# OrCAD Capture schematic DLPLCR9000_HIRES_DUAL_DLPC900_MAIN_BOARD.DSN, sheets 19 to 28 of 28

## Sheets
19 P01-Title
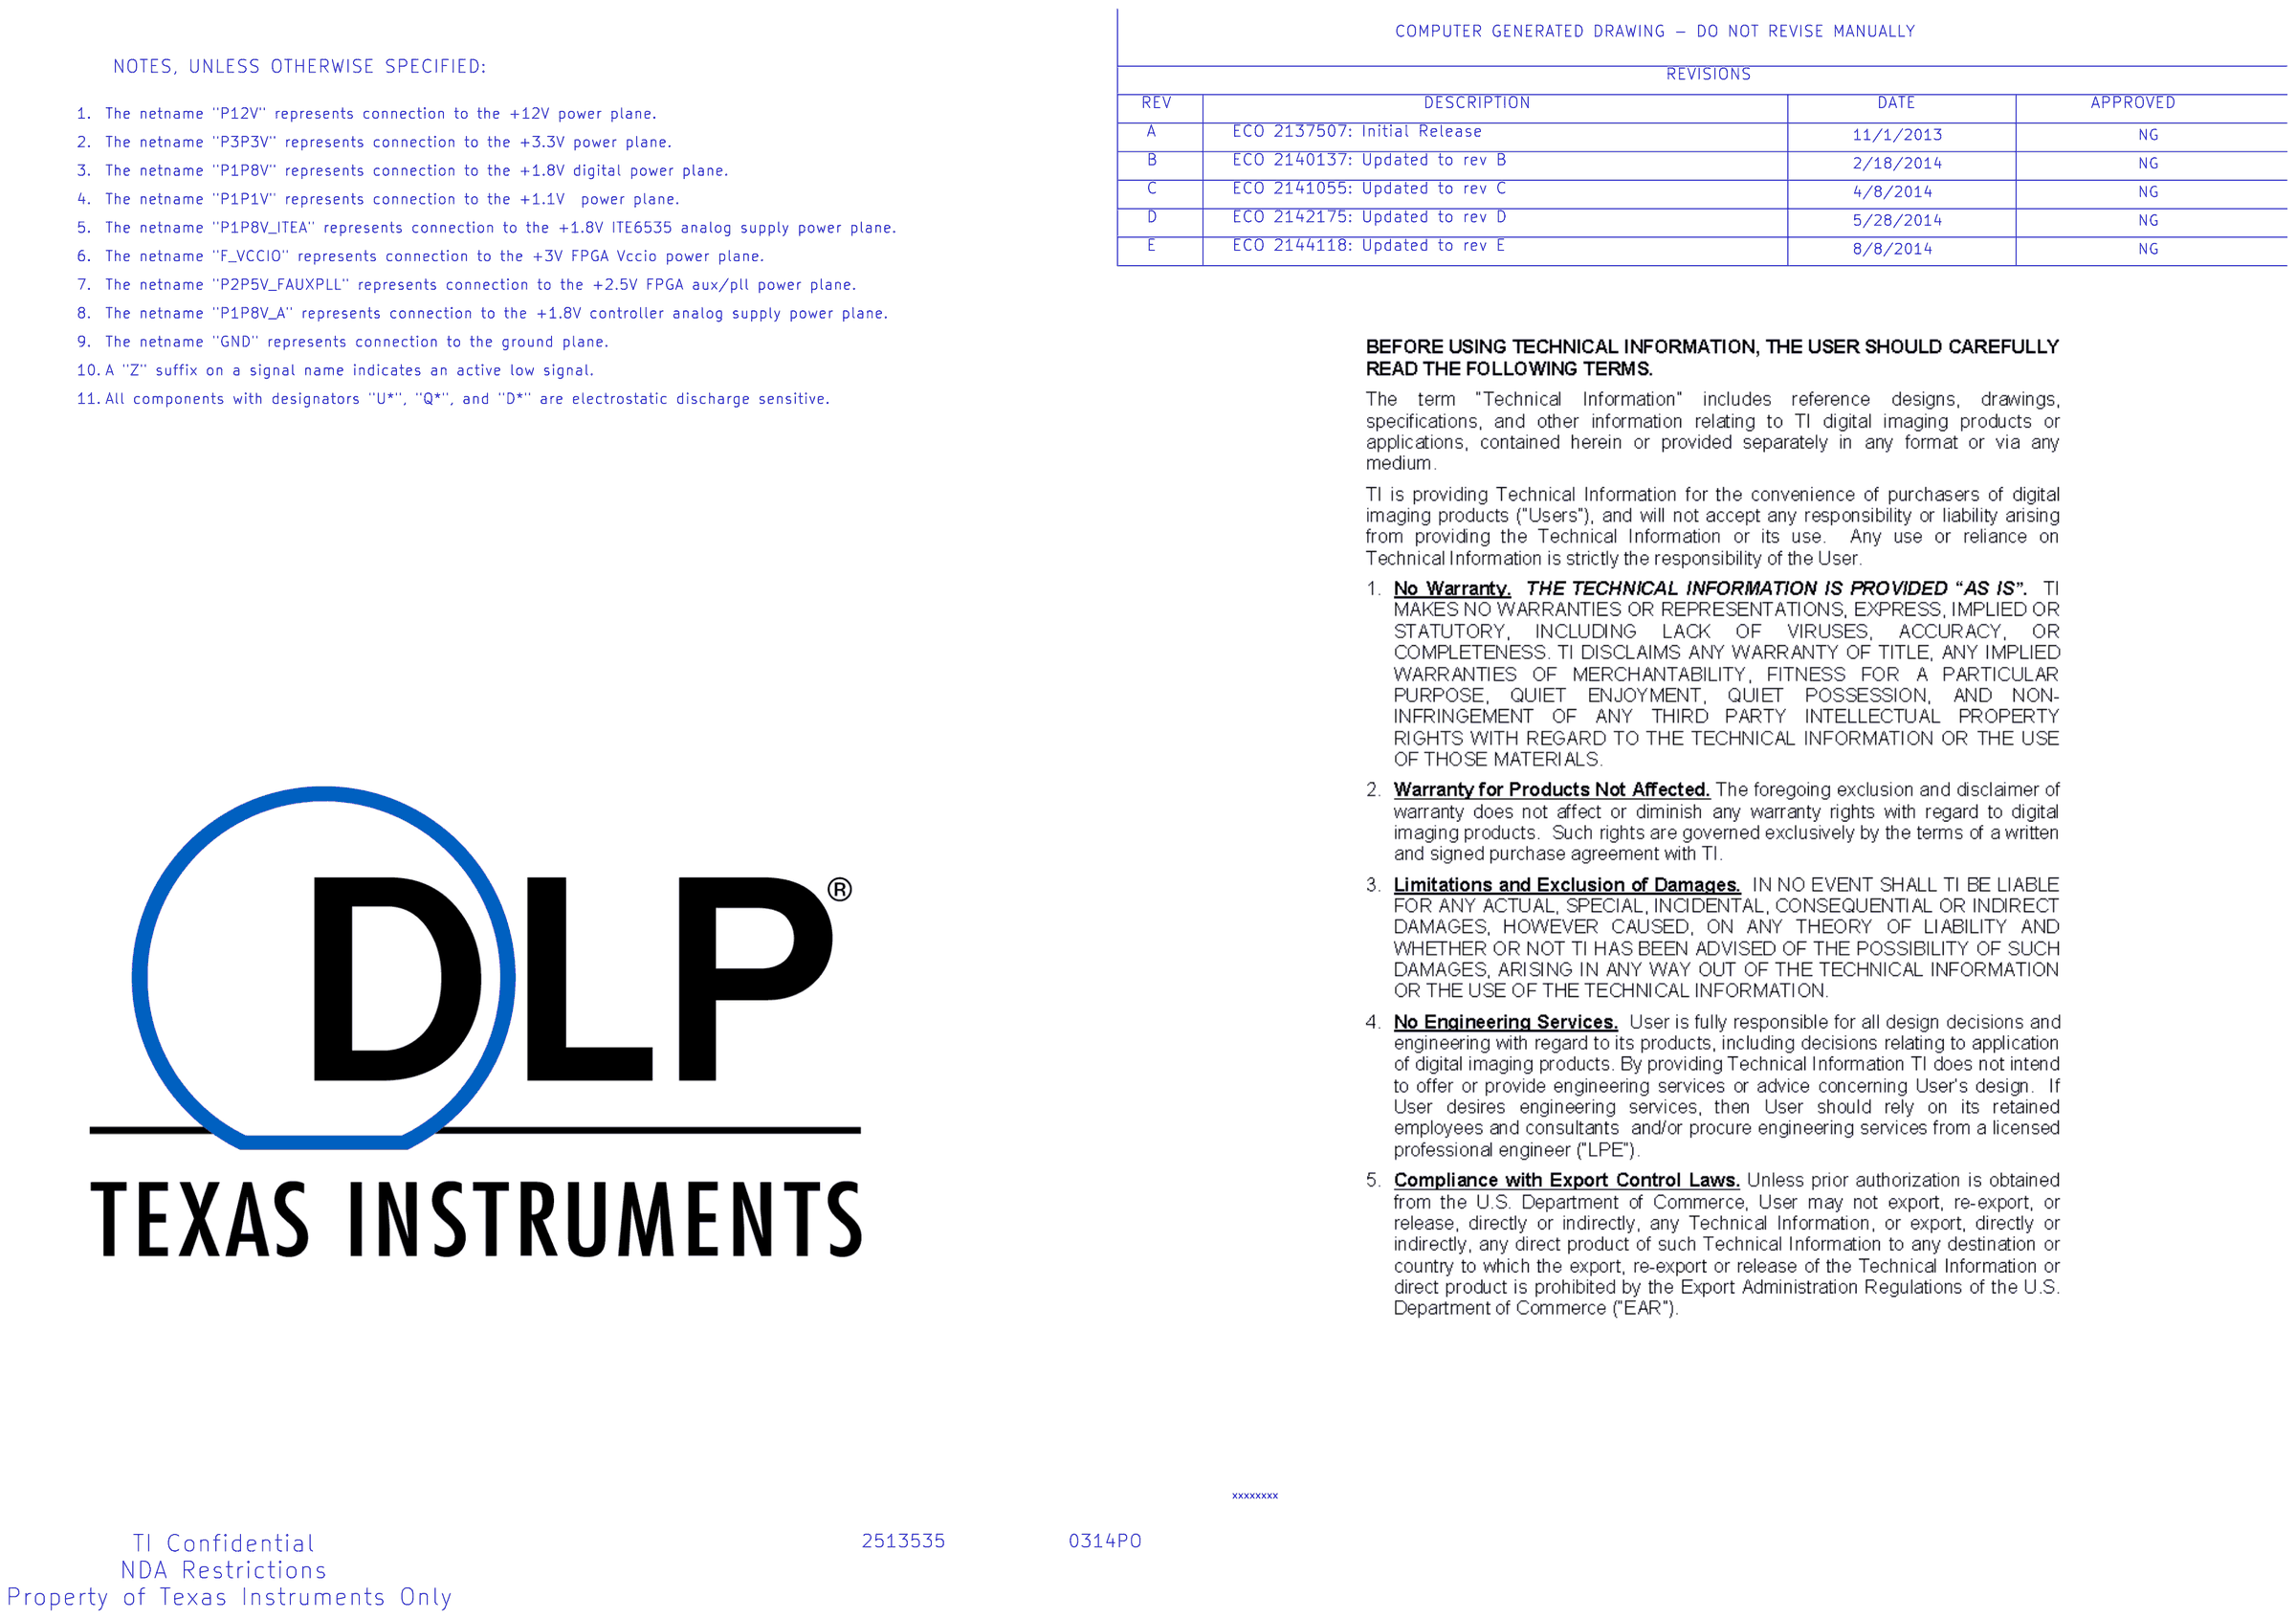
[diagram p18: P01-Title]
20 P03-Table Of Contents
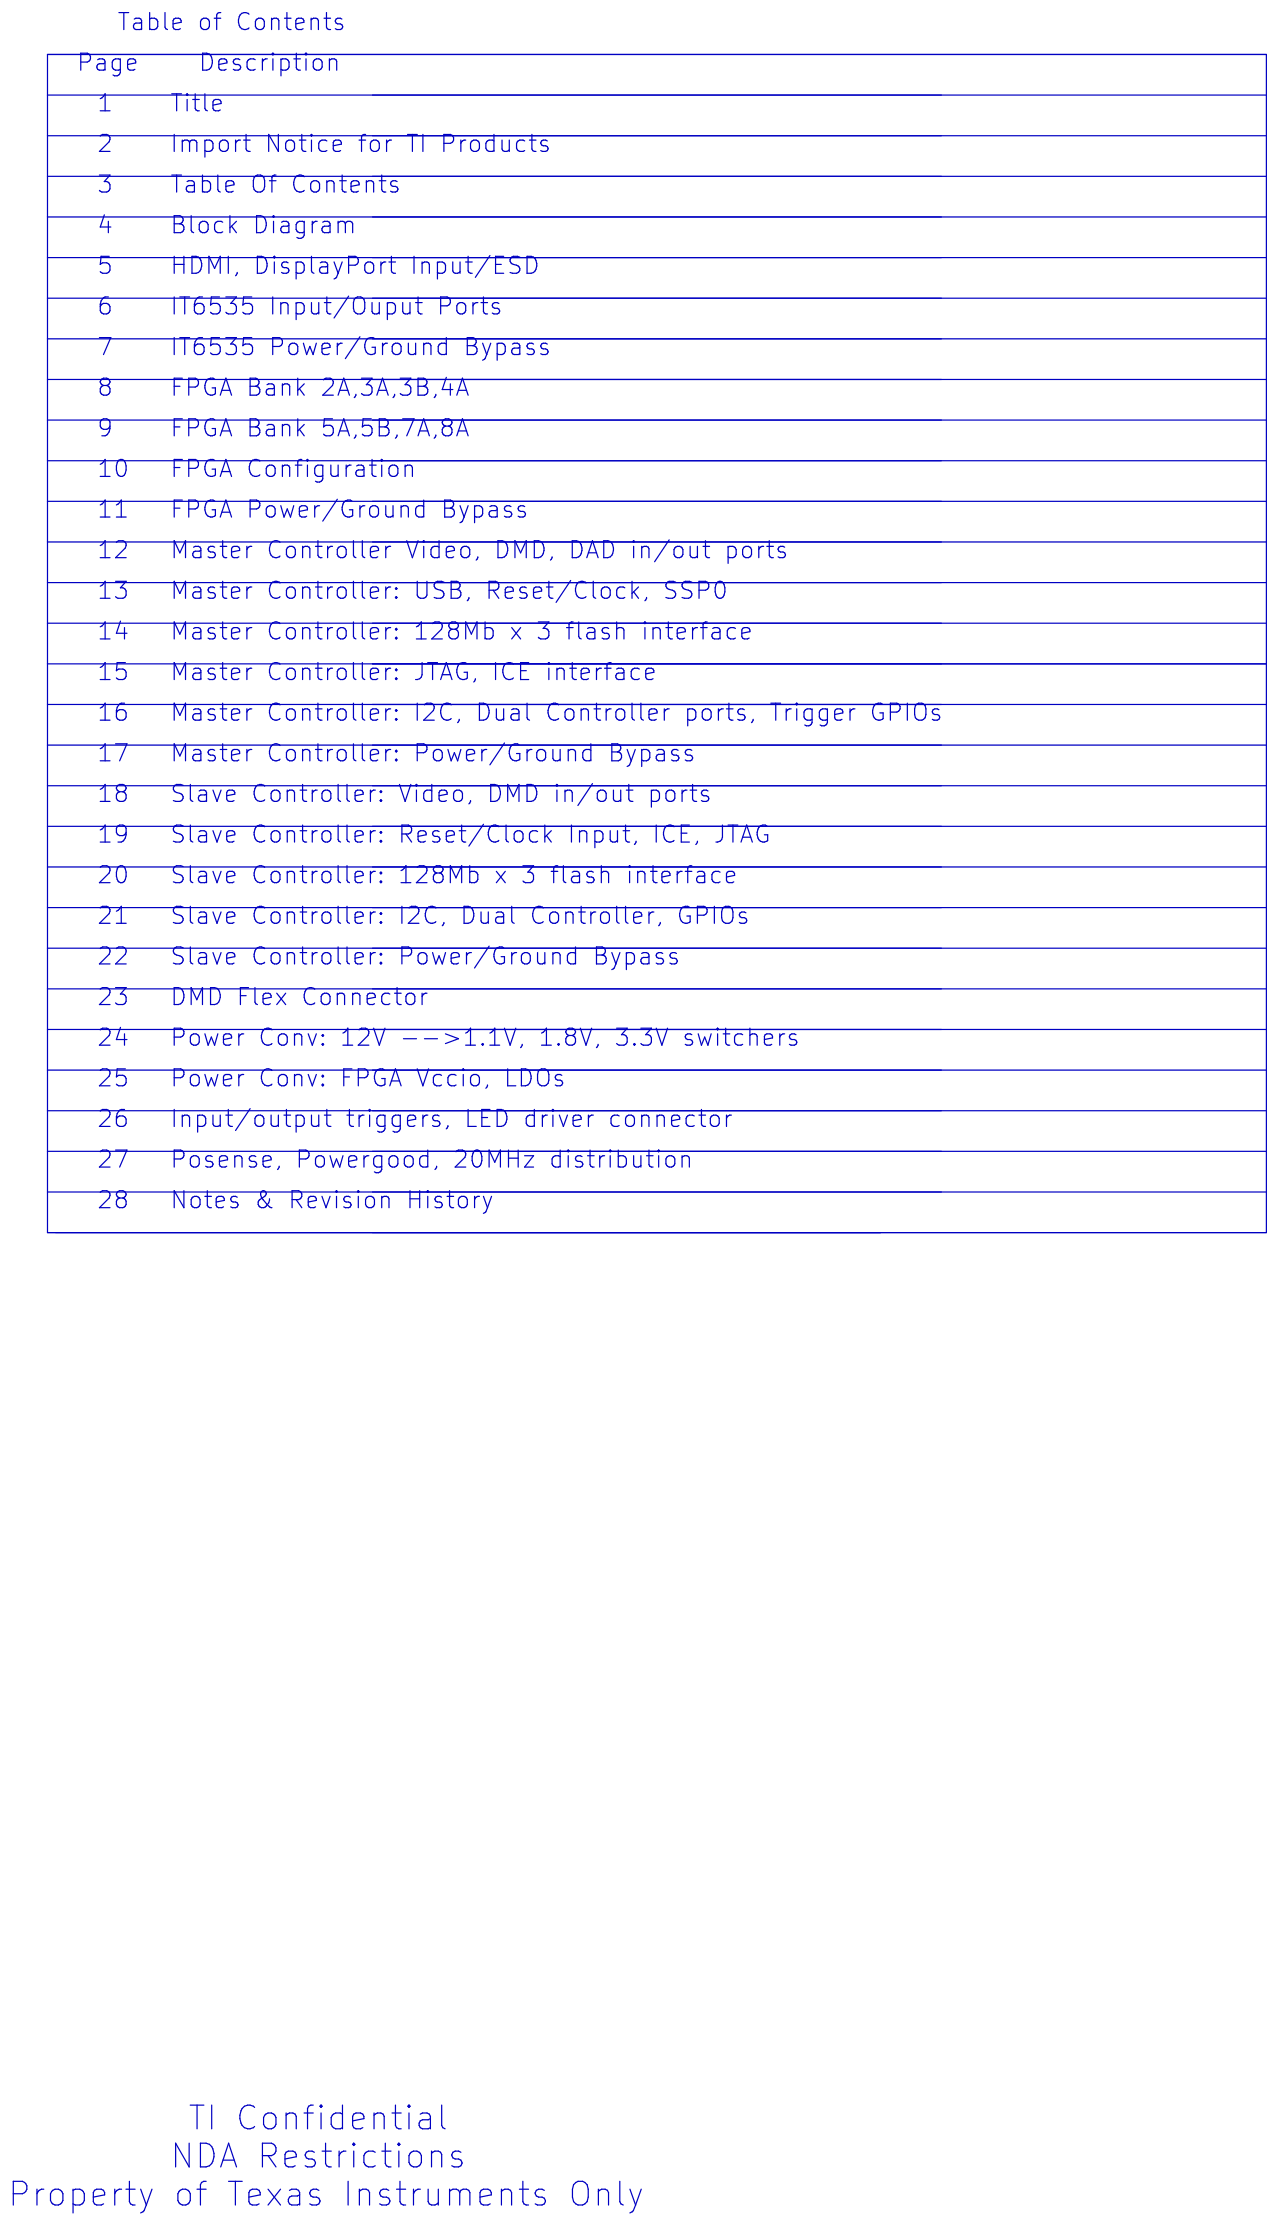
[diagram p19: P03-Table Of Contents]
21 P04-Block Diagram
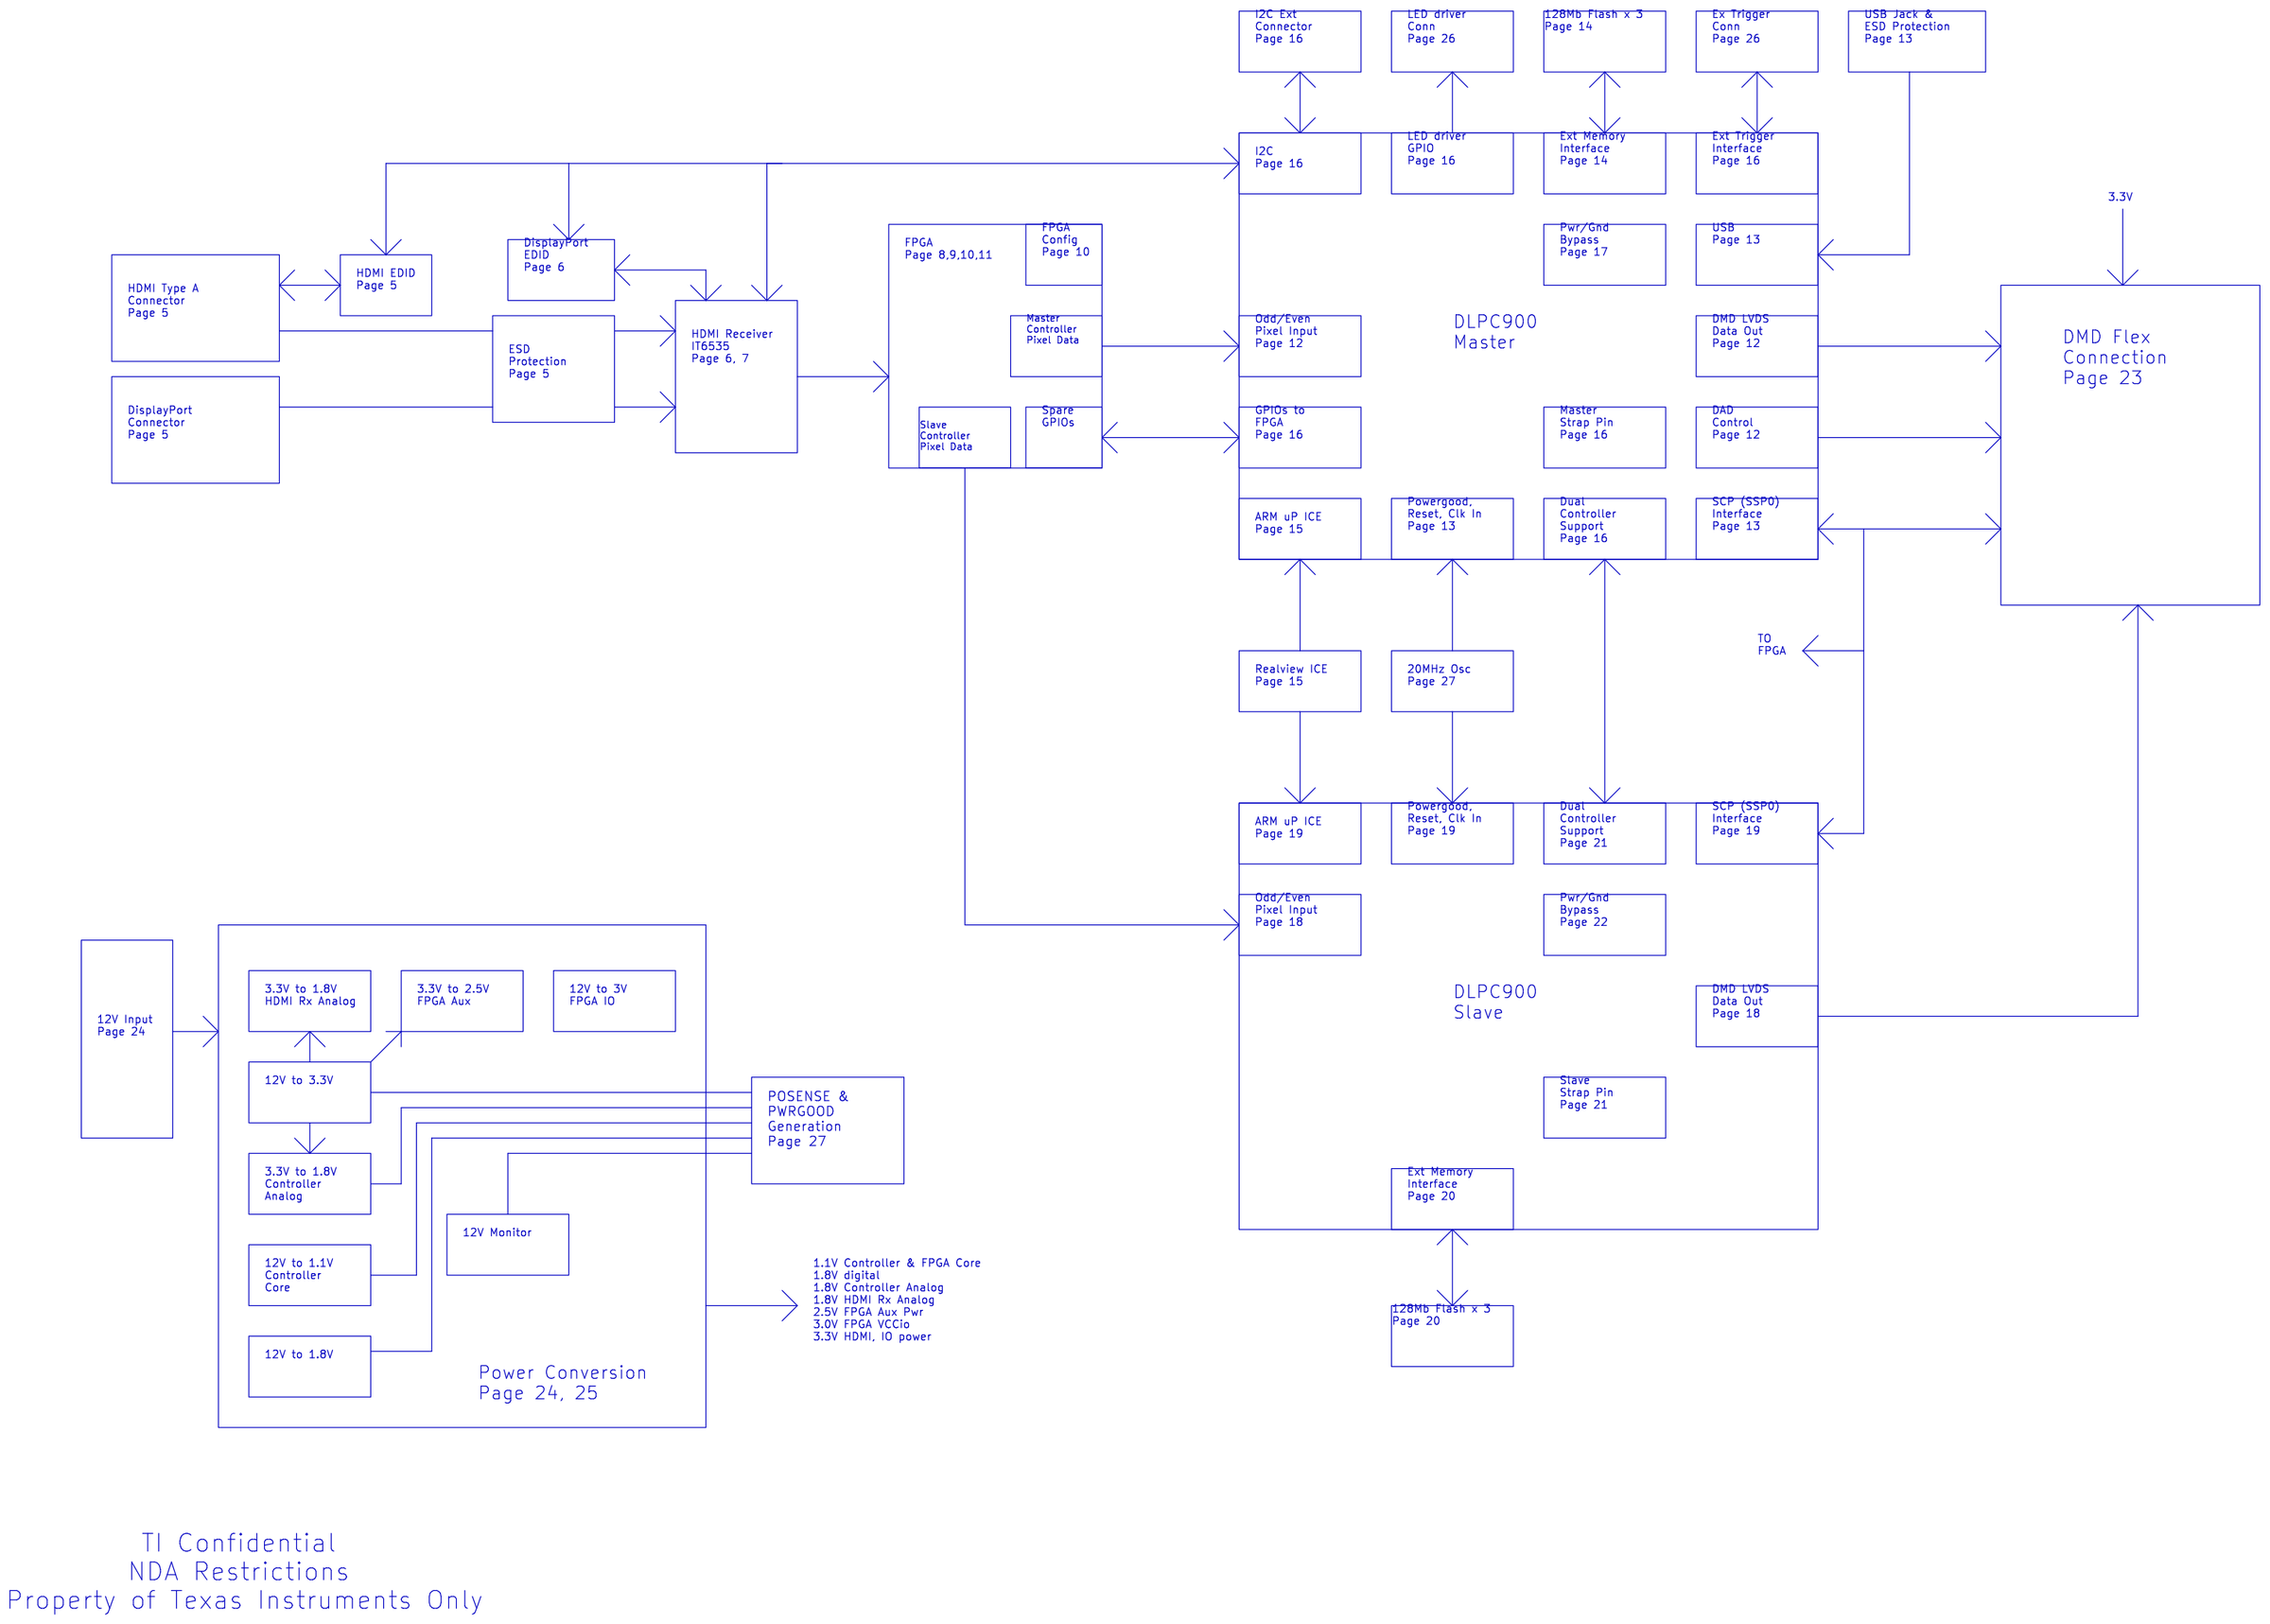
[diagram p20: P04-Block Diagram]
22 P06-IT6535 Input Output Ports: size A3
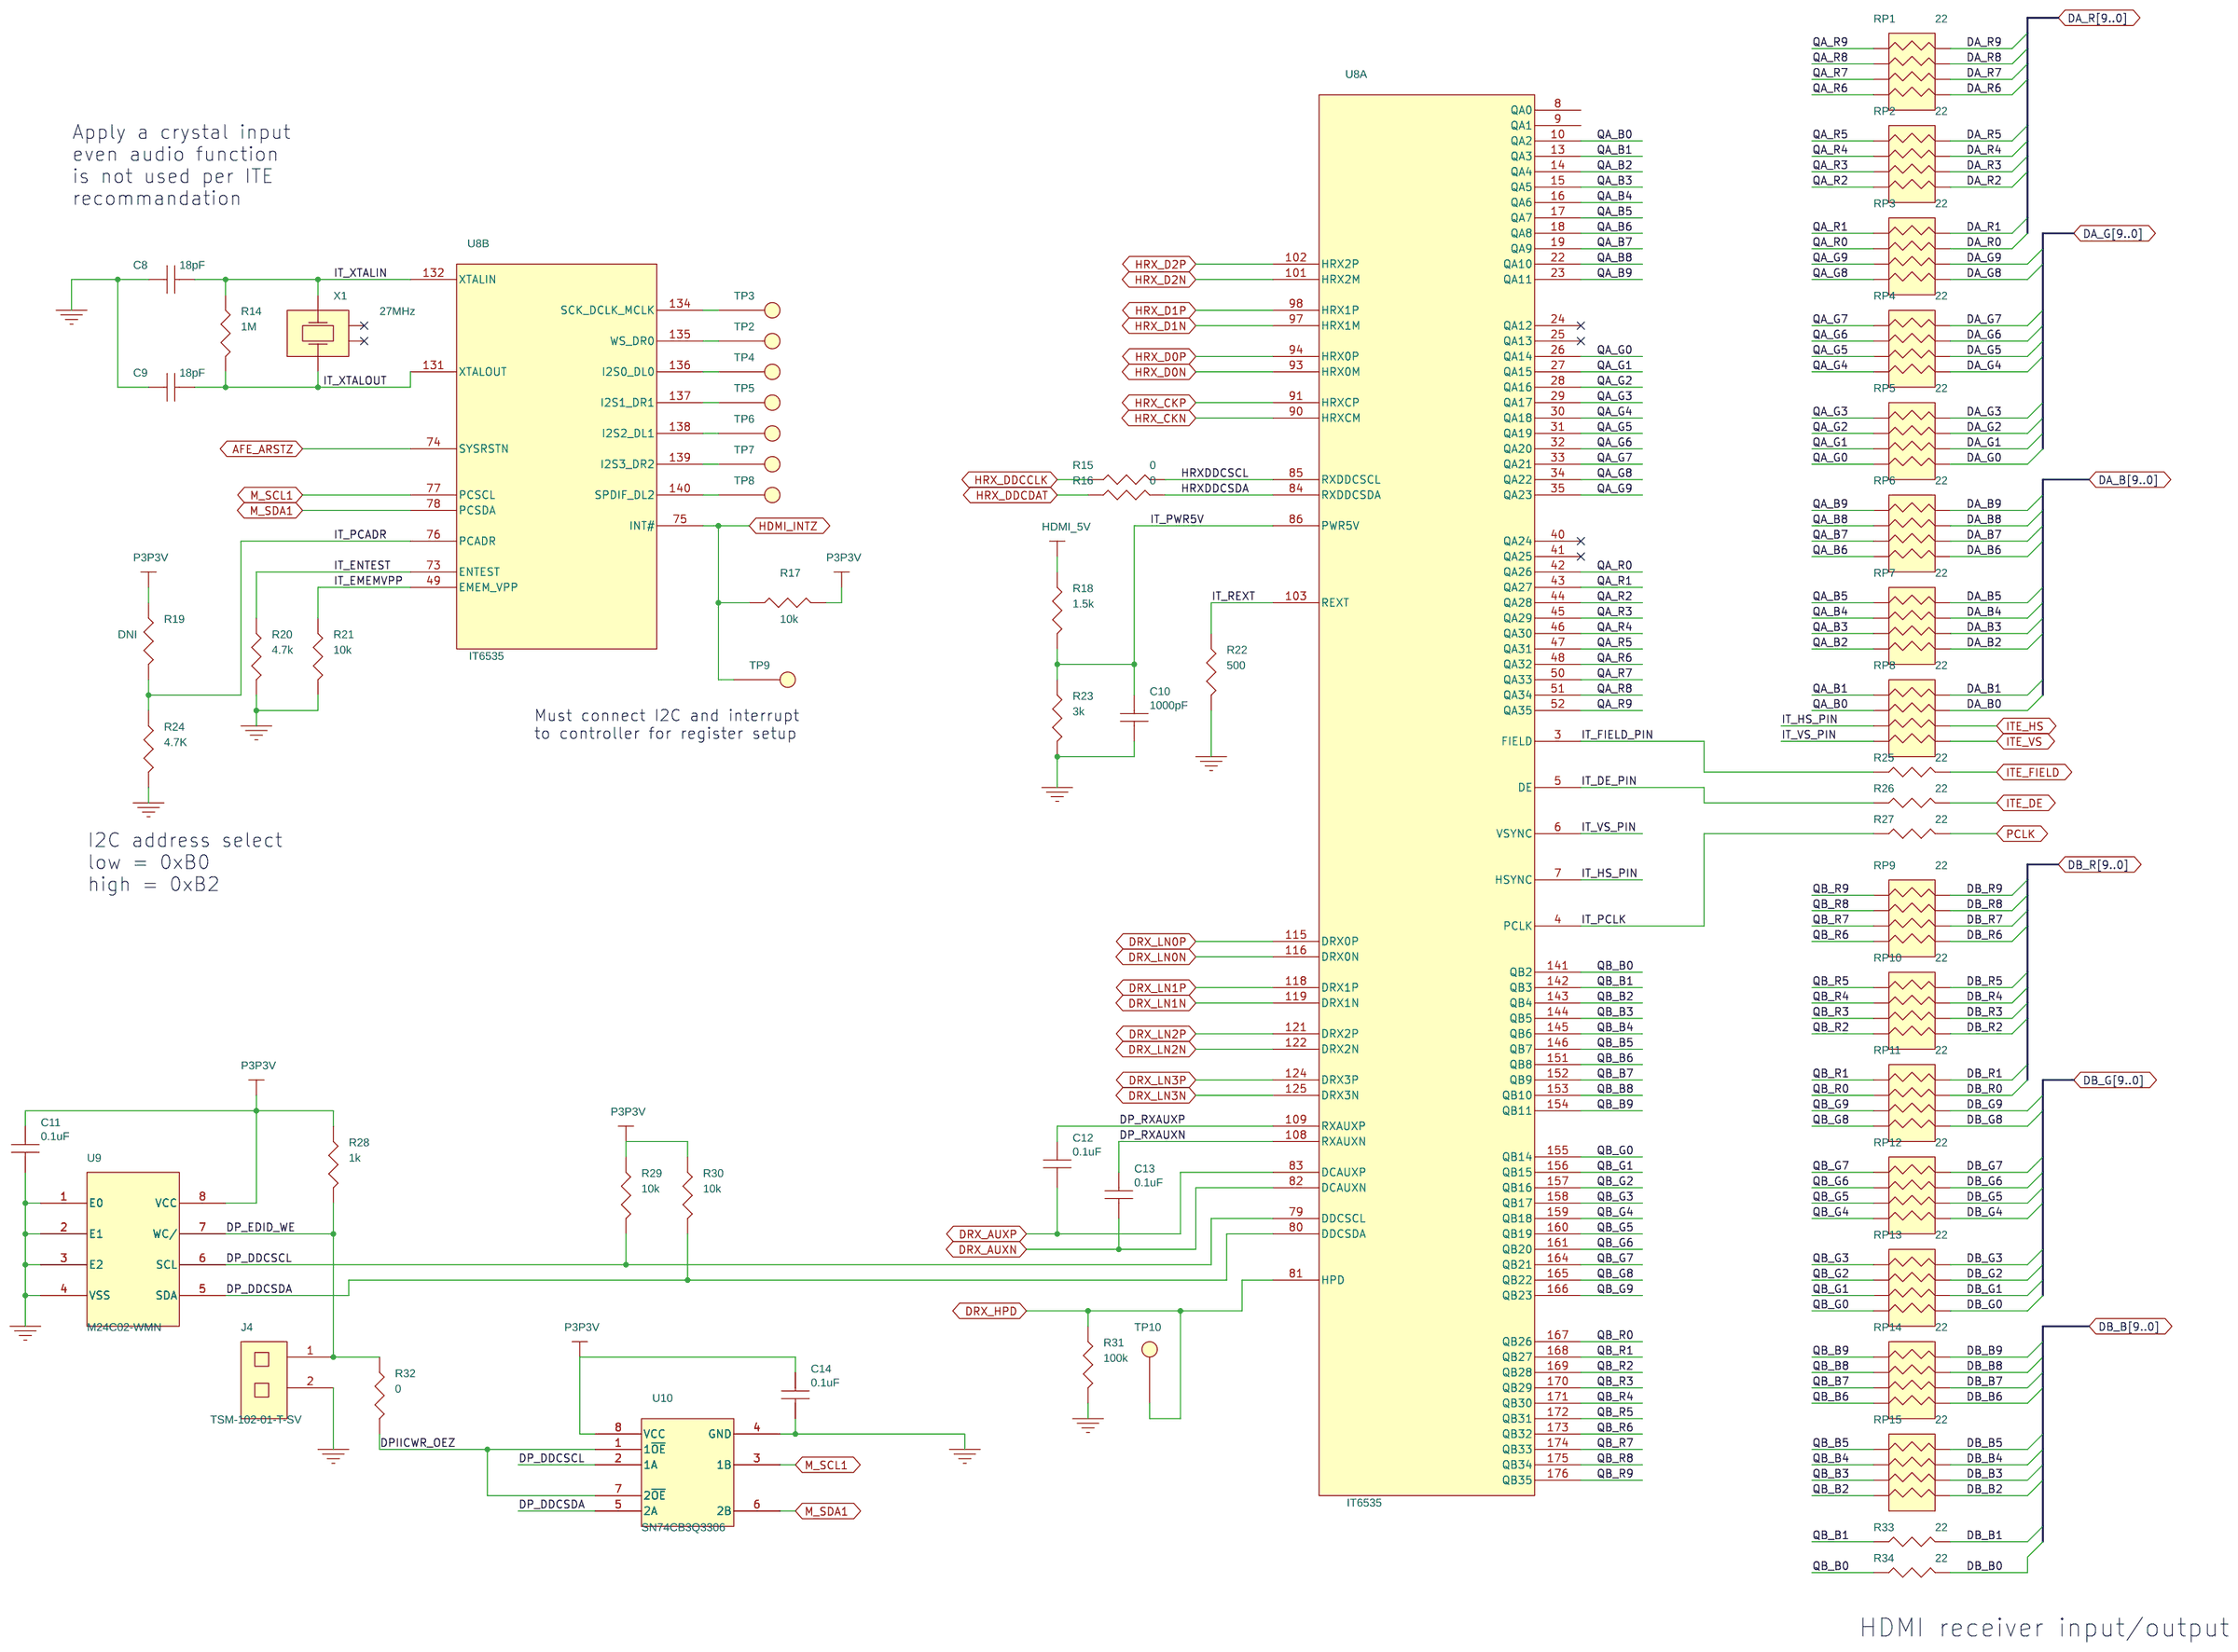
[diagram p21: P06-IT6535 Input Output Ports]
23 P28-Notes and Revision
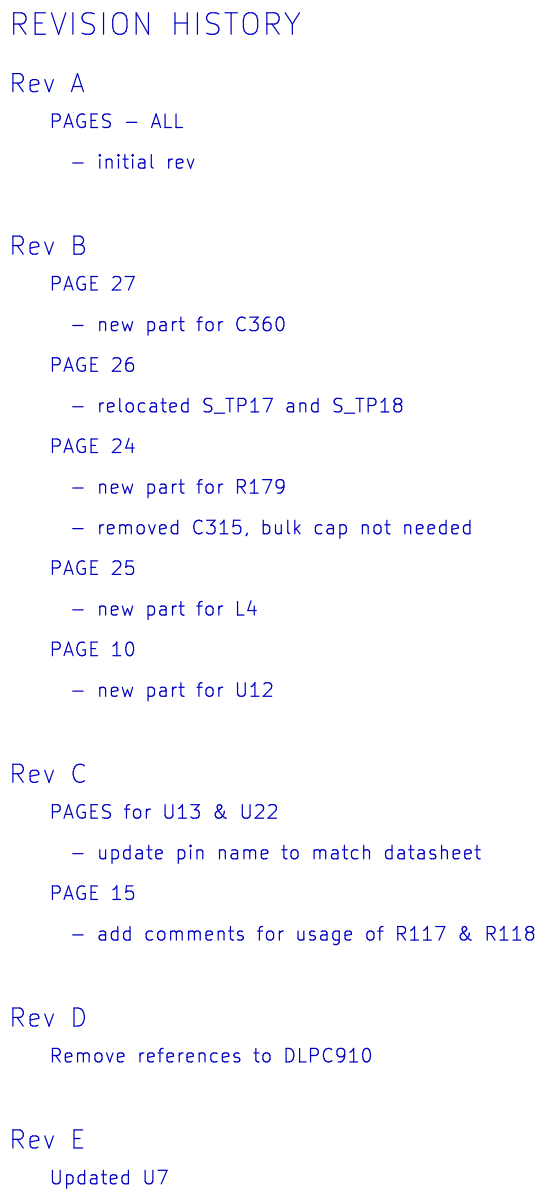
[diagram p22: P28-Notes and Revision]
24 P07-IT6535 Pwr/Gnd: size A3
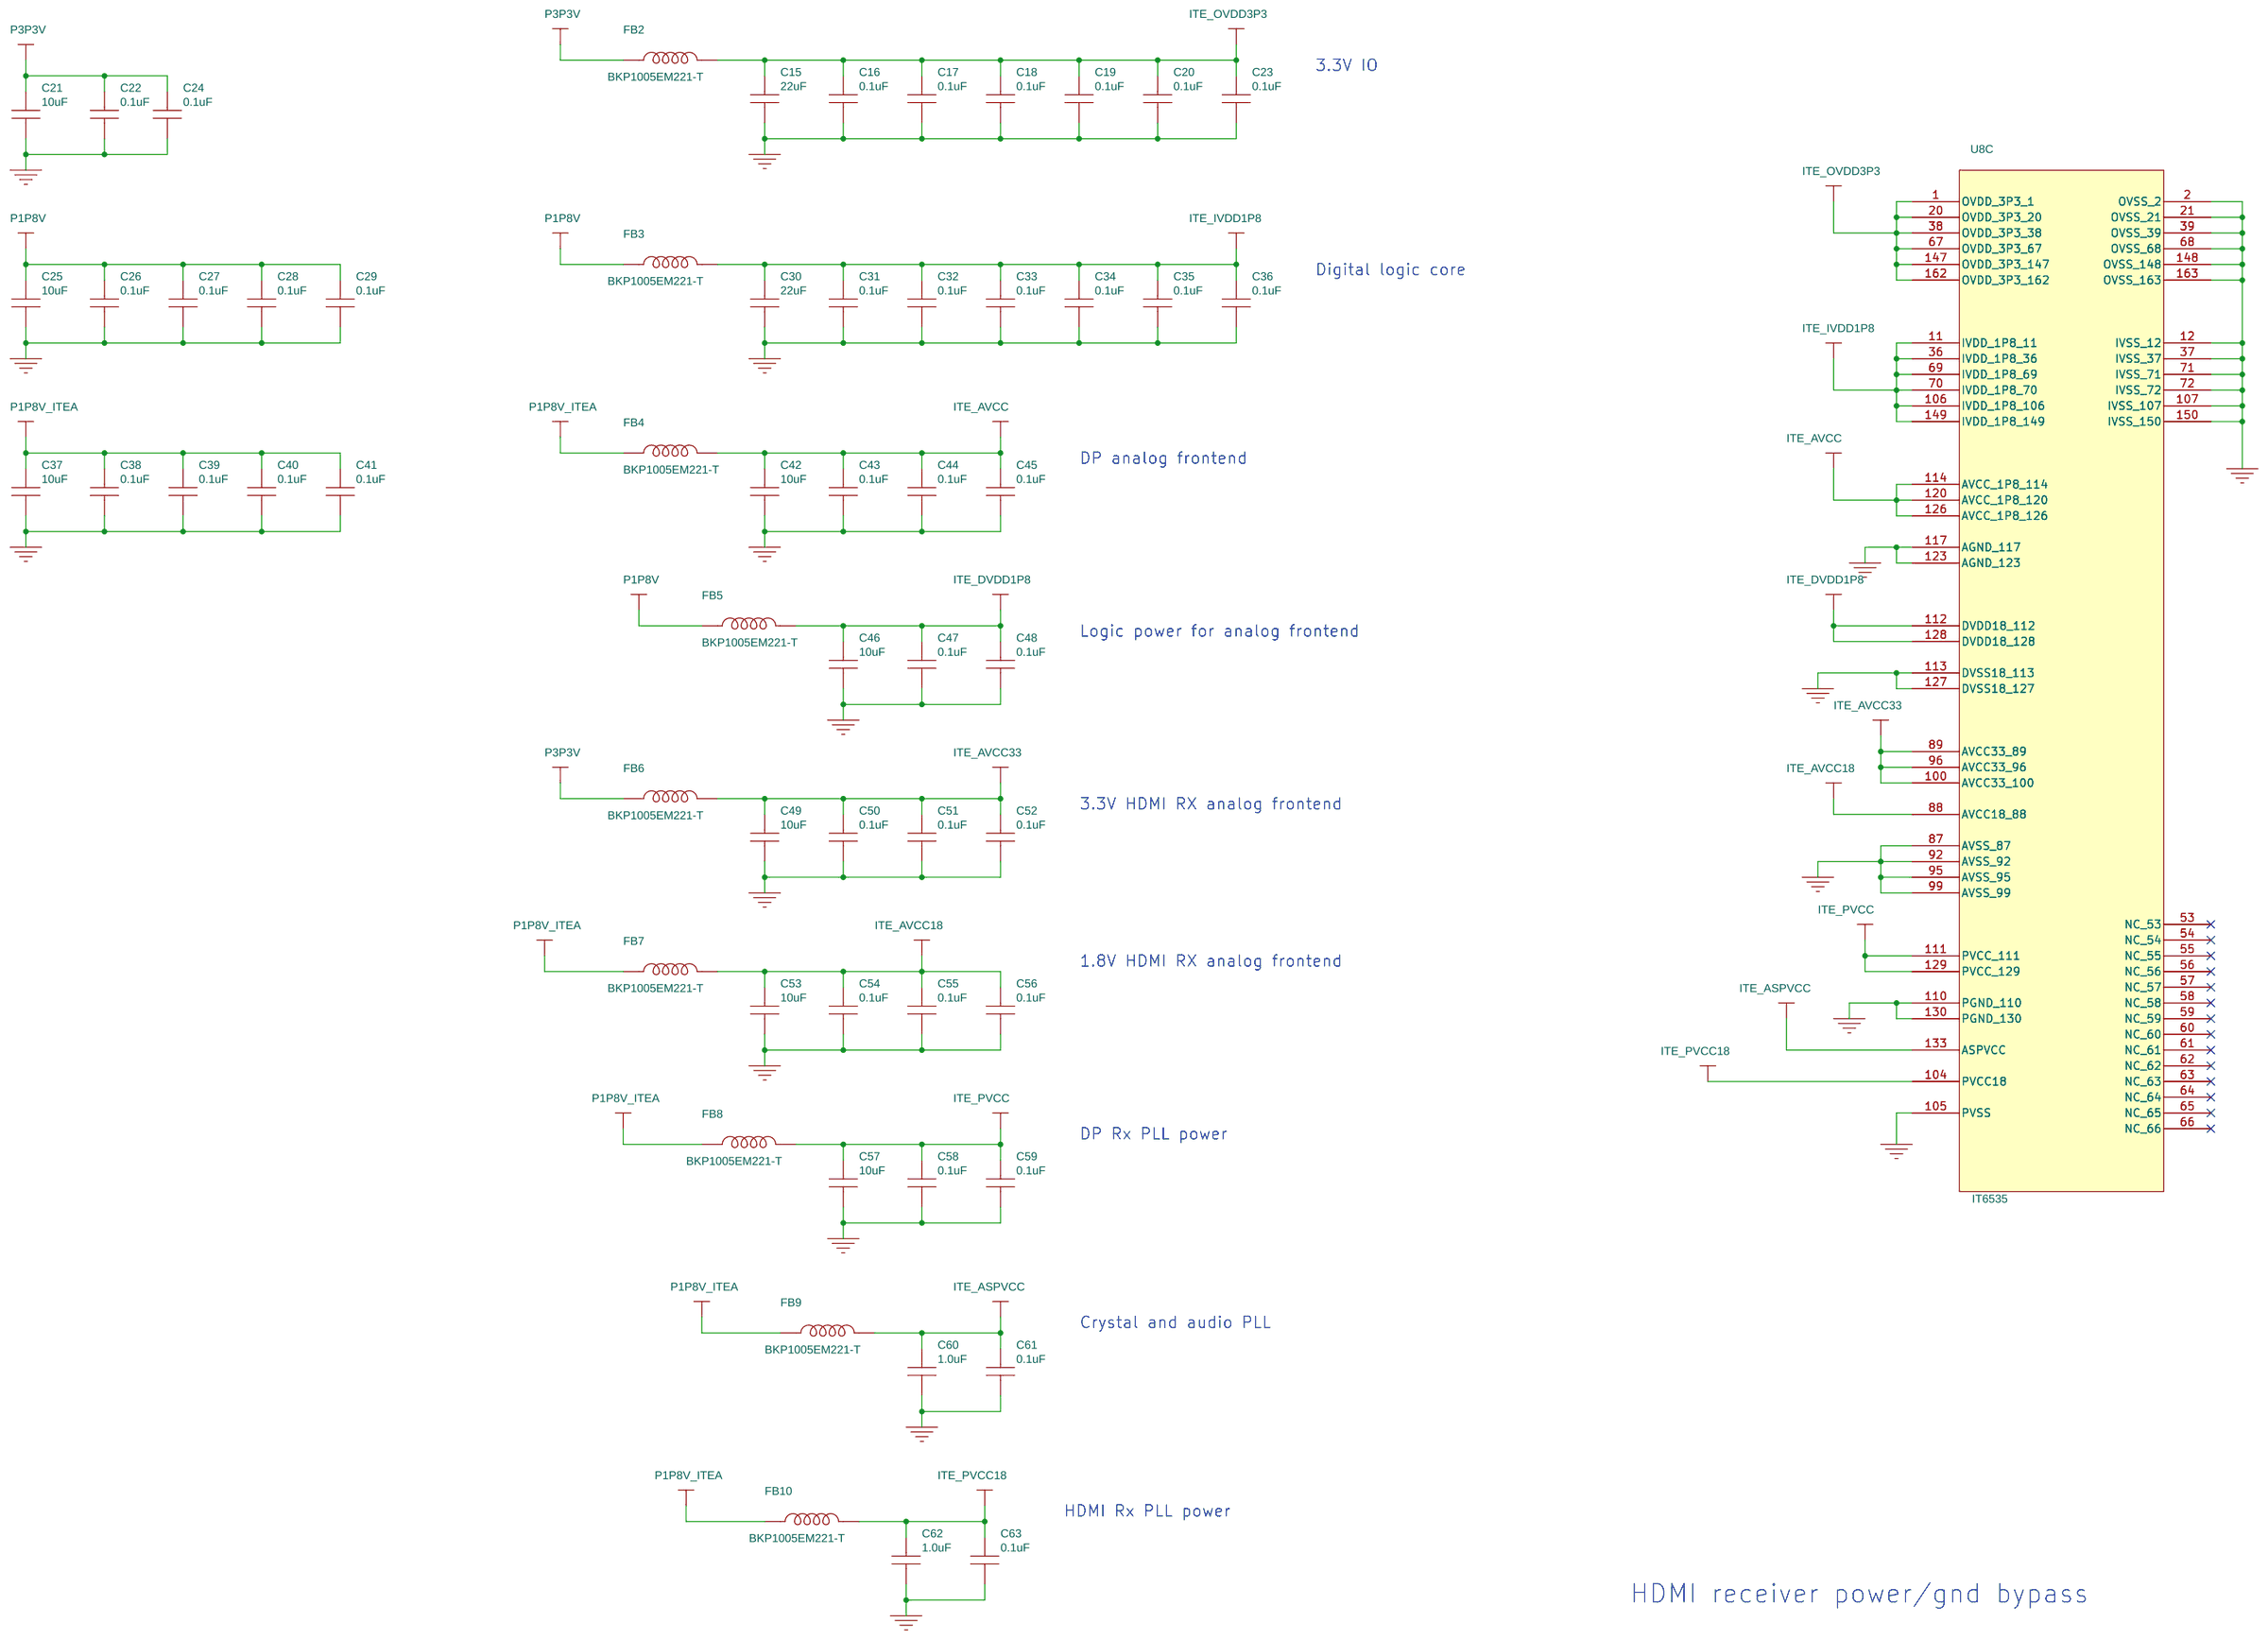
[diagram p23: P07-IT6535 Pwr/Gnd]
25 P11-FPGA Pwr/Gnd: size A3
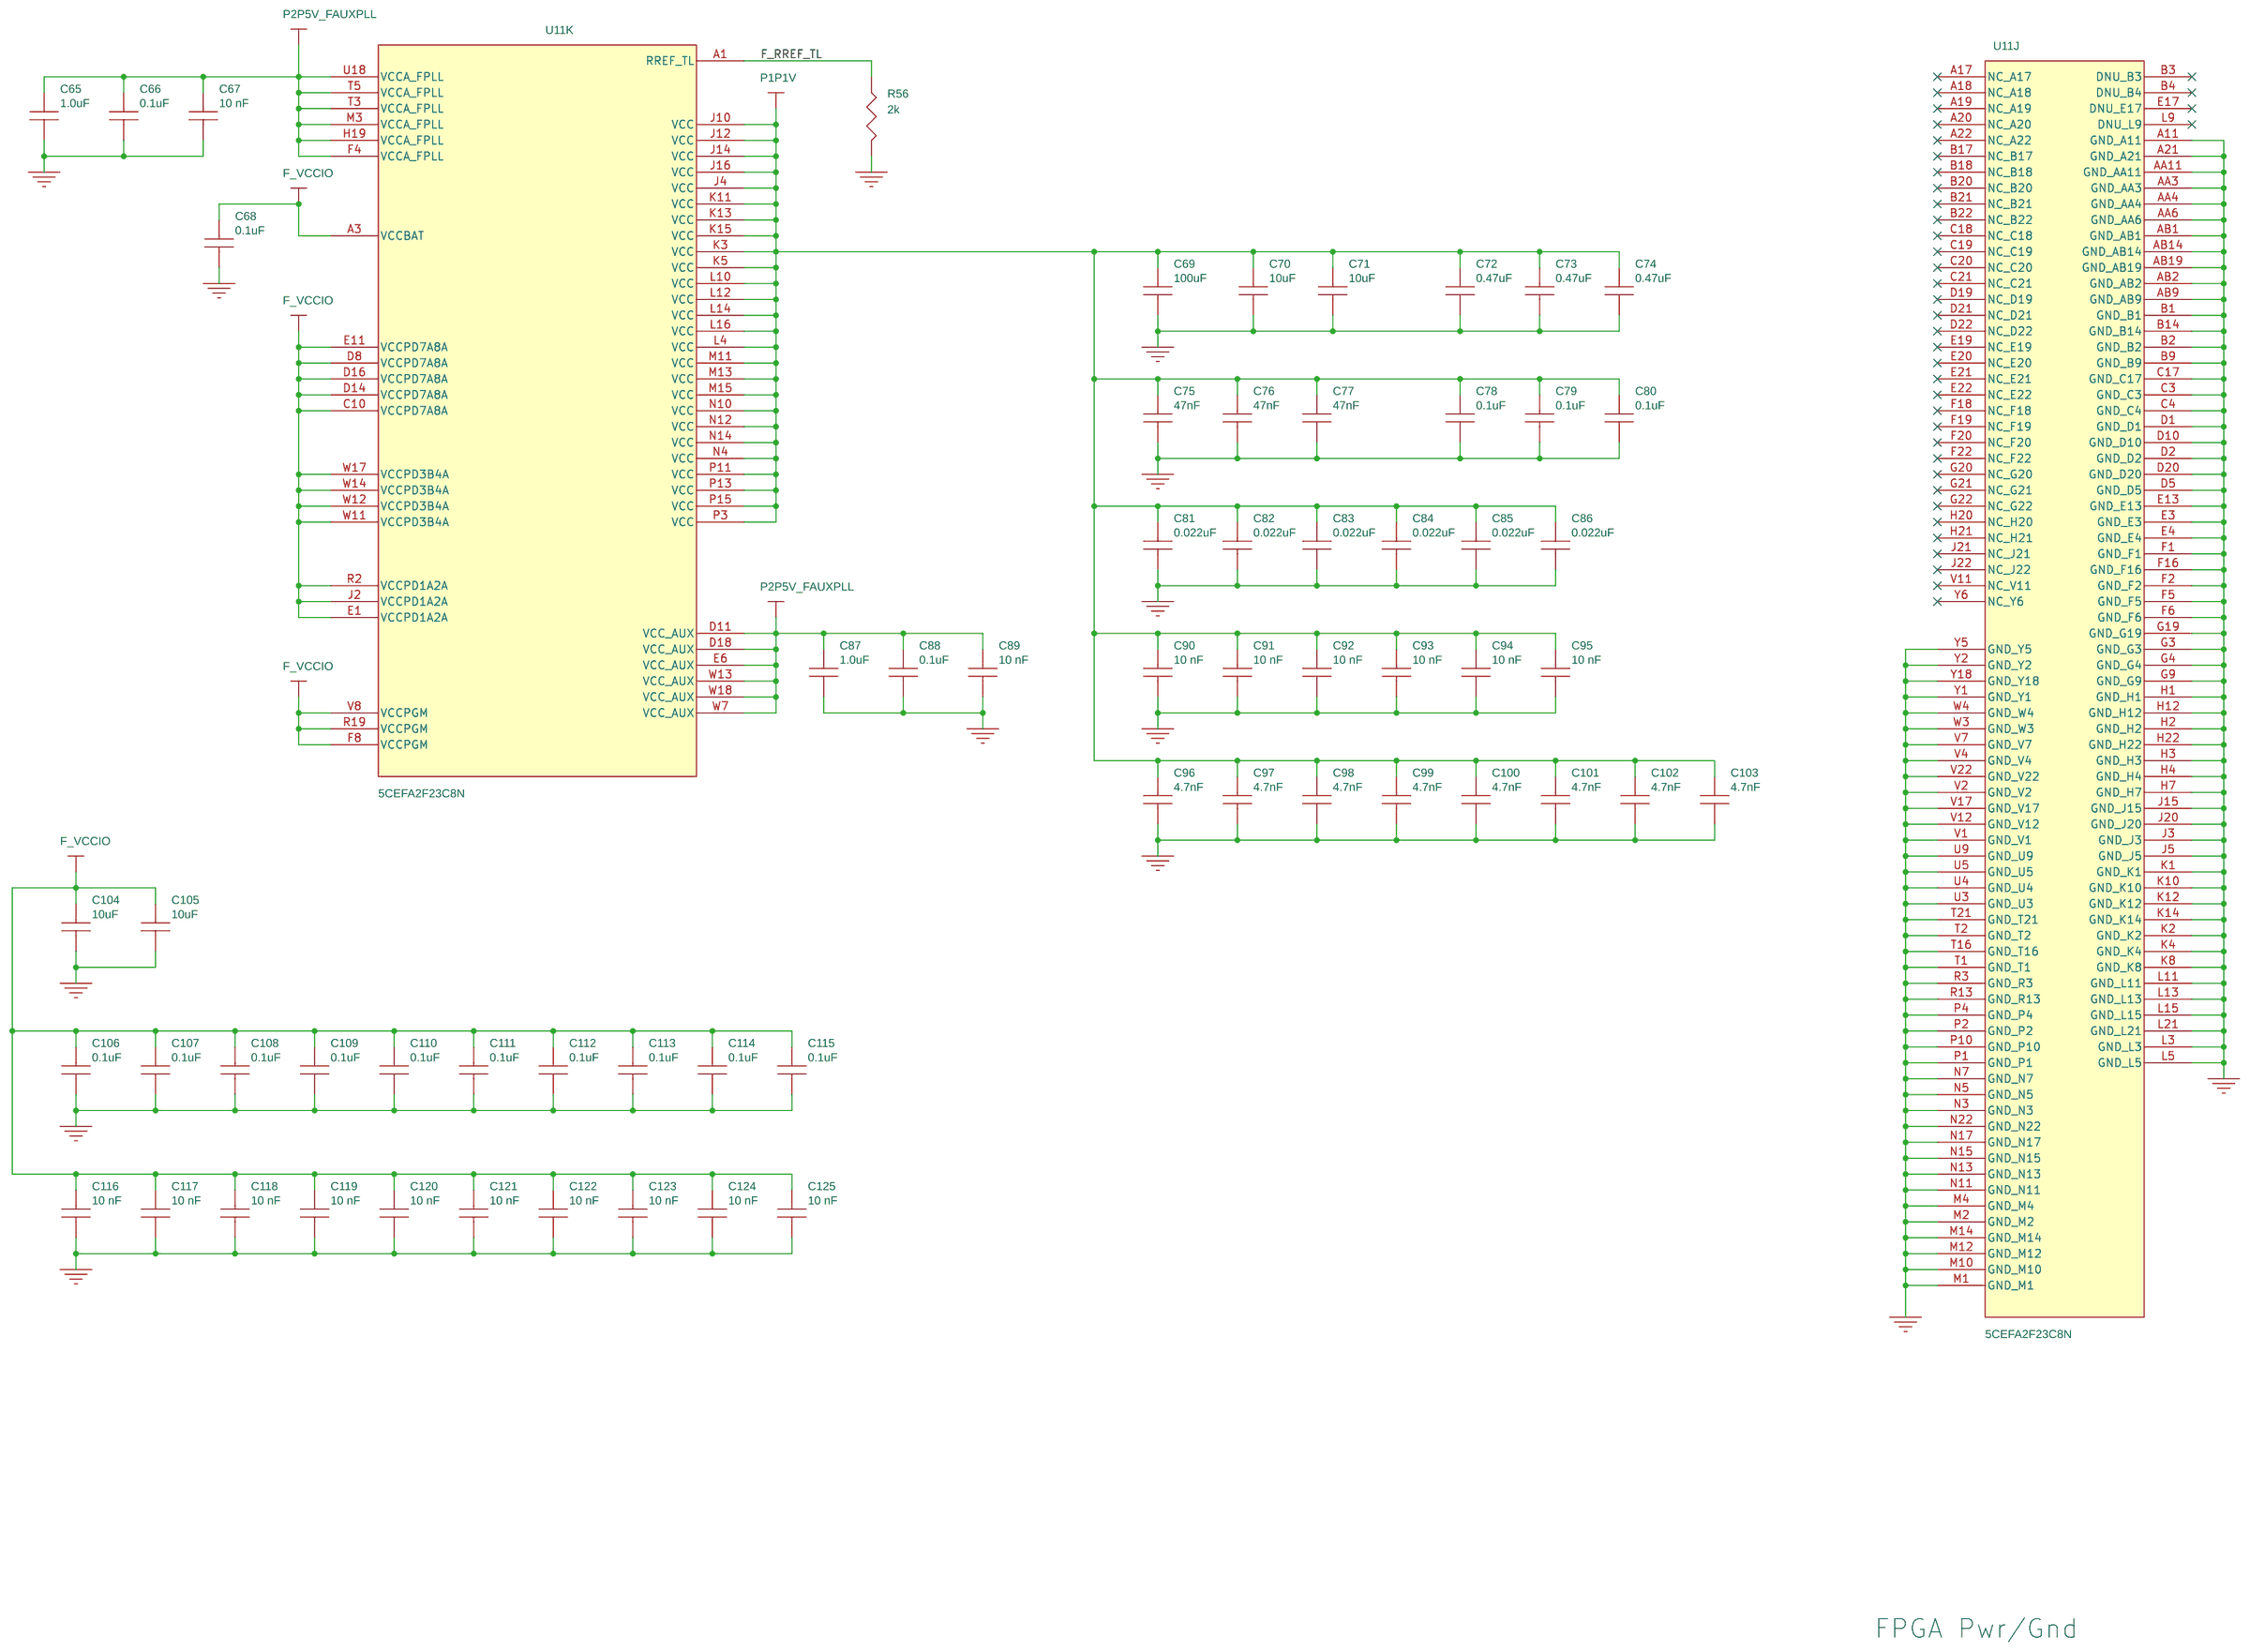
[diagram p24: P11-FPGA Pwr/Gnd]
26 P22-Slave Pwr/Gnd: size A3
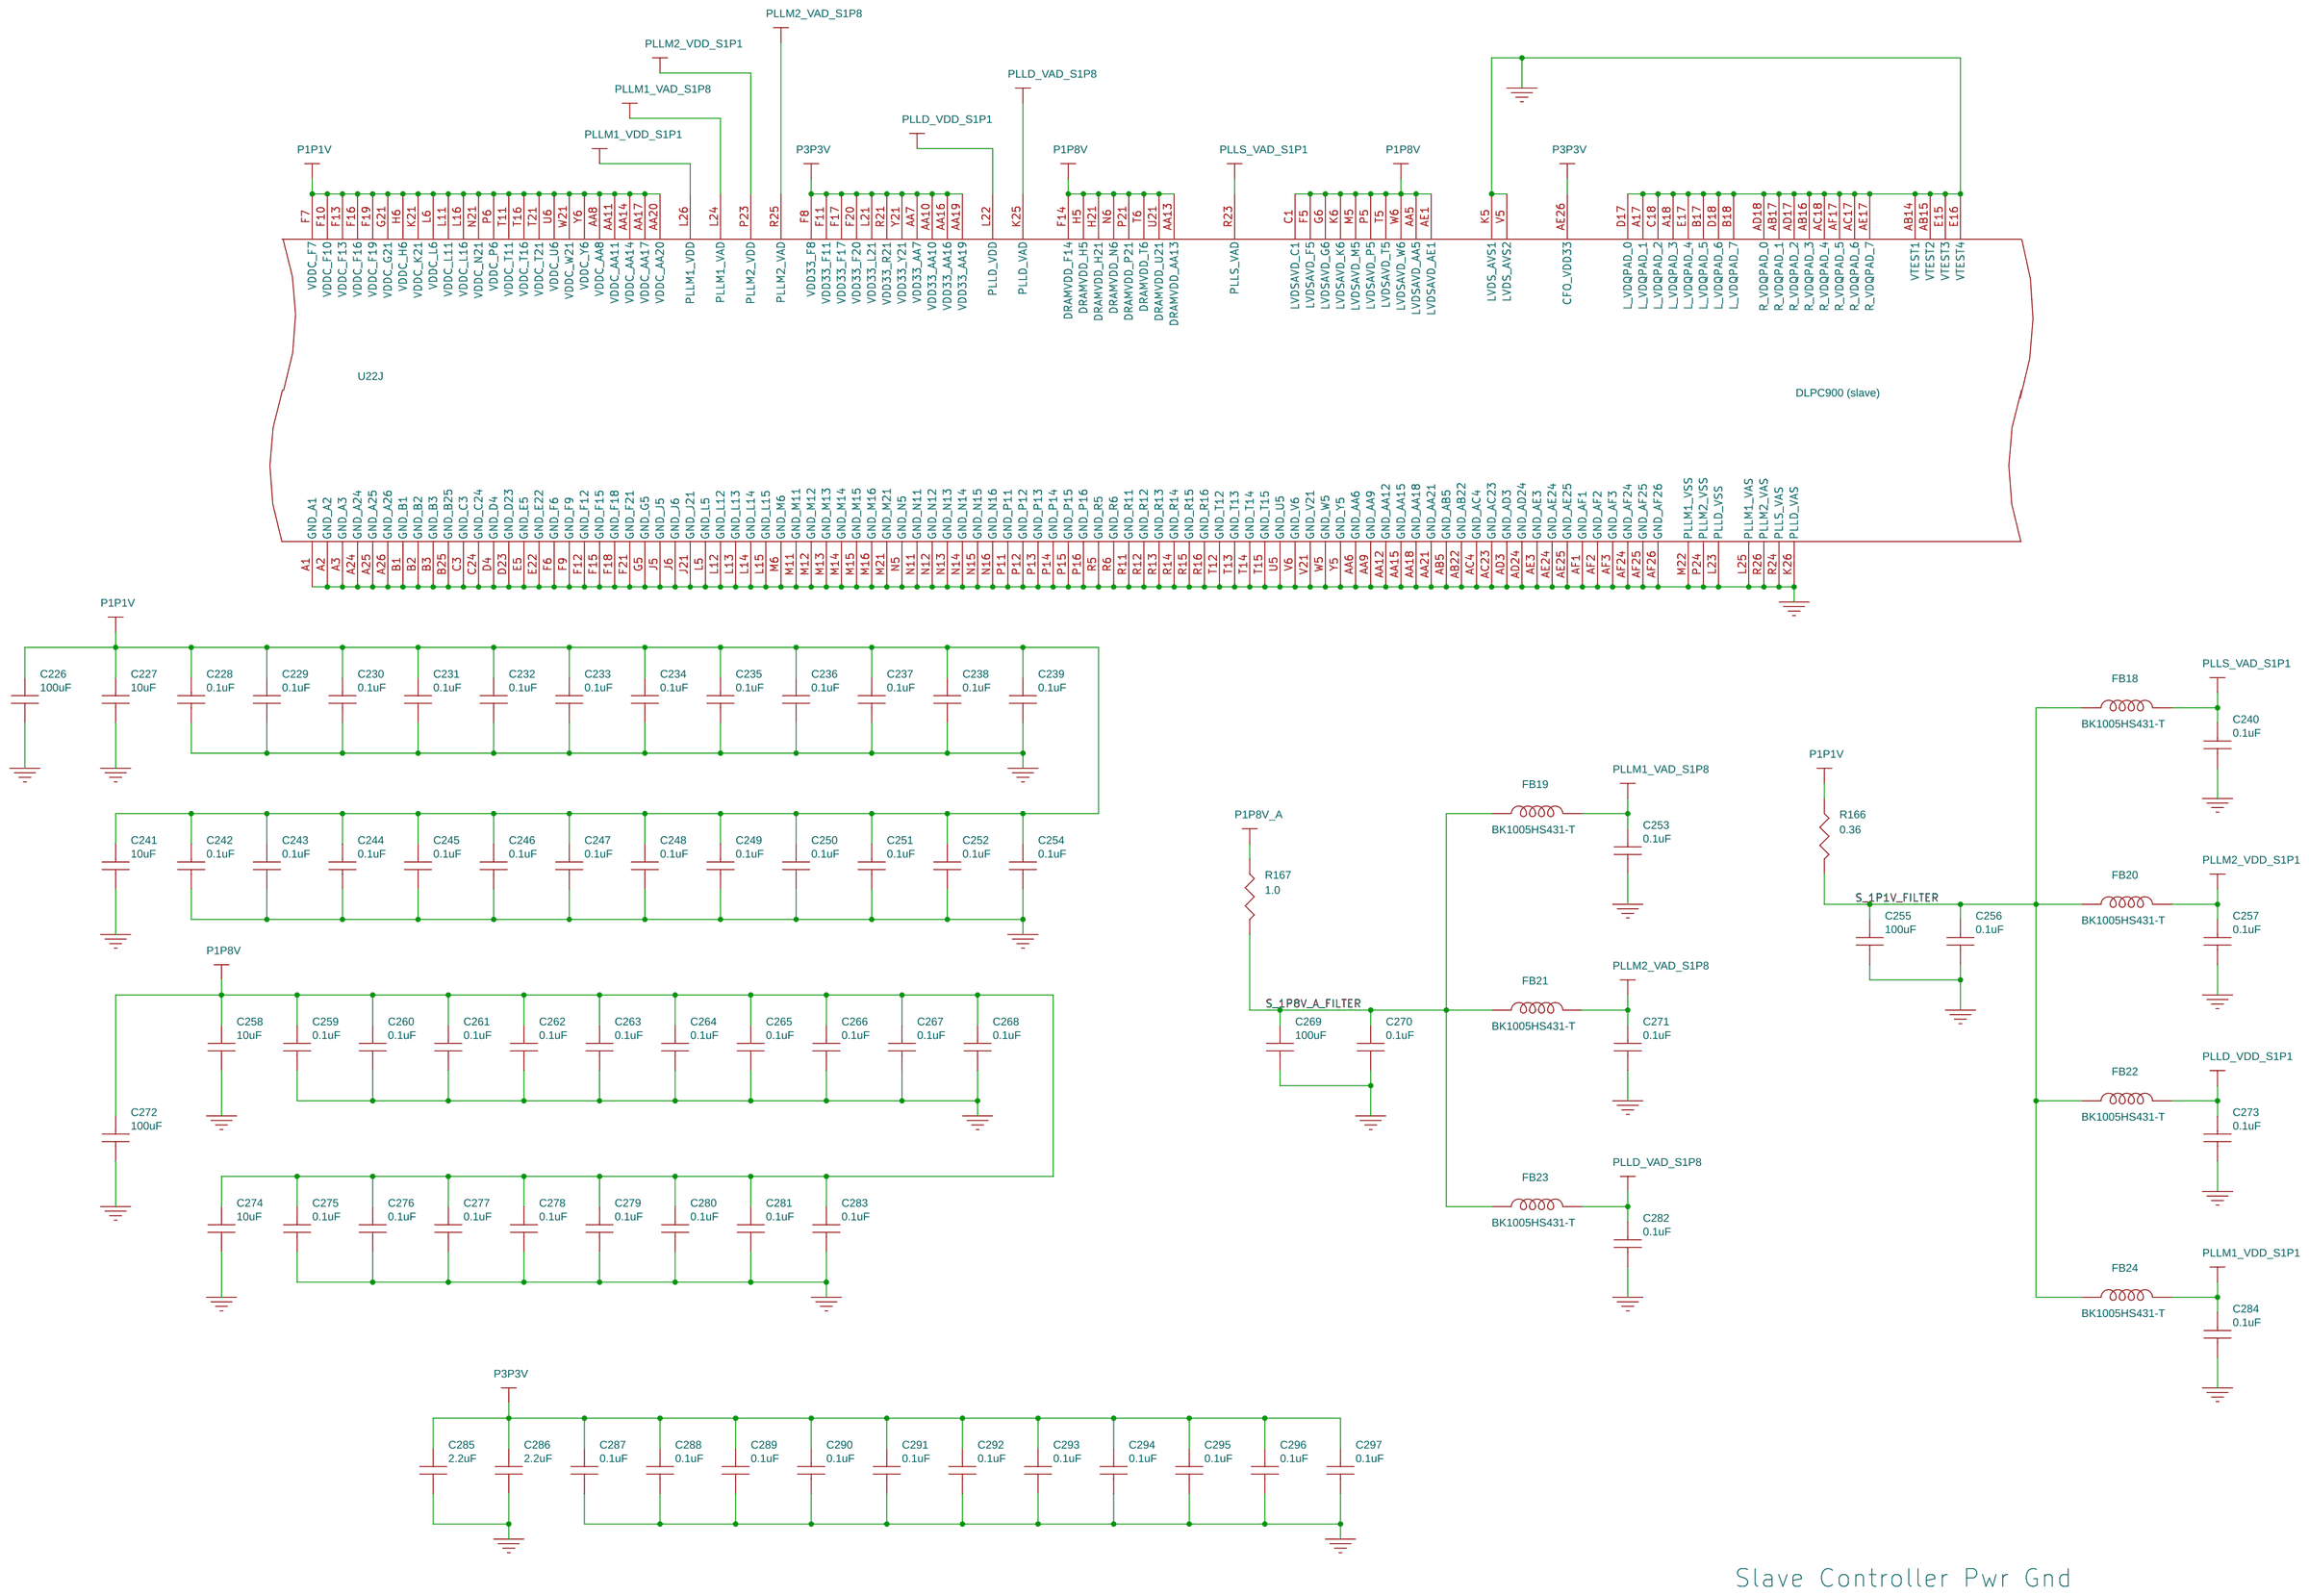
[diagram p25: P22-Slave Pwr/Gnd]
27 P17-Master Pwr/Gnd: size A3
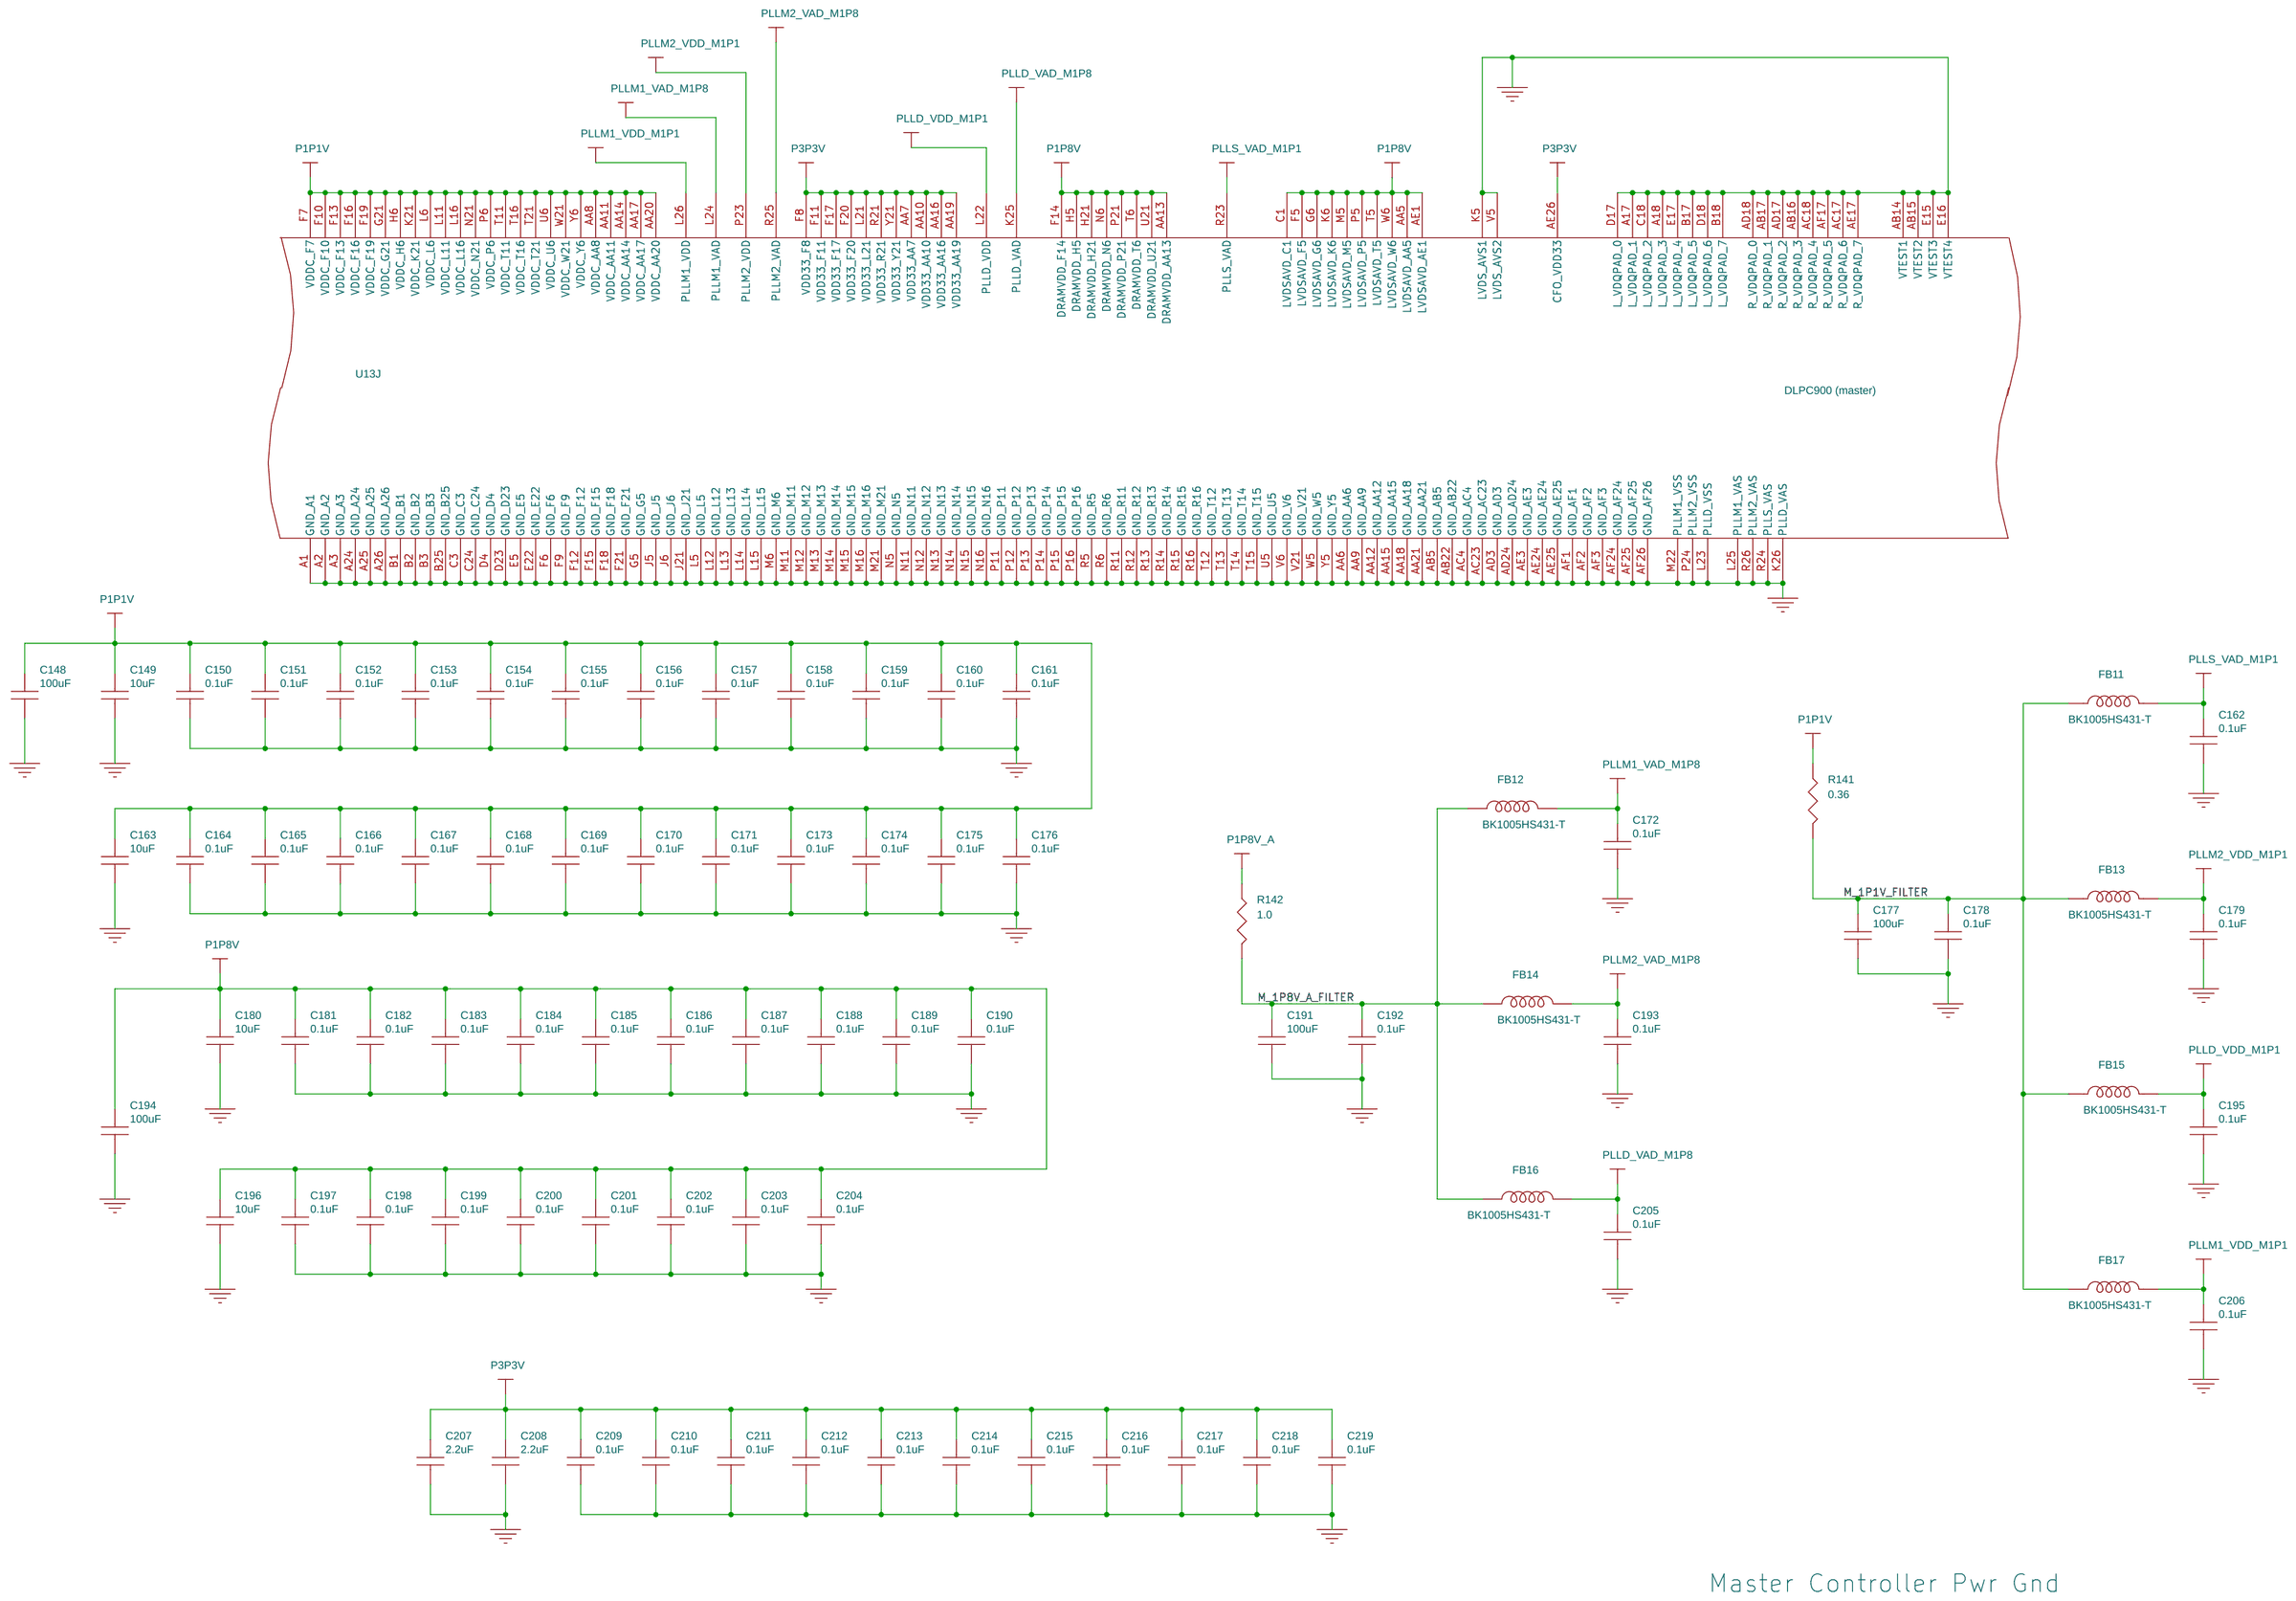
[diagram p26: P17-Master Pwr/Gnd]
28 P05-HDMI/DP Conn, ESD: size A3
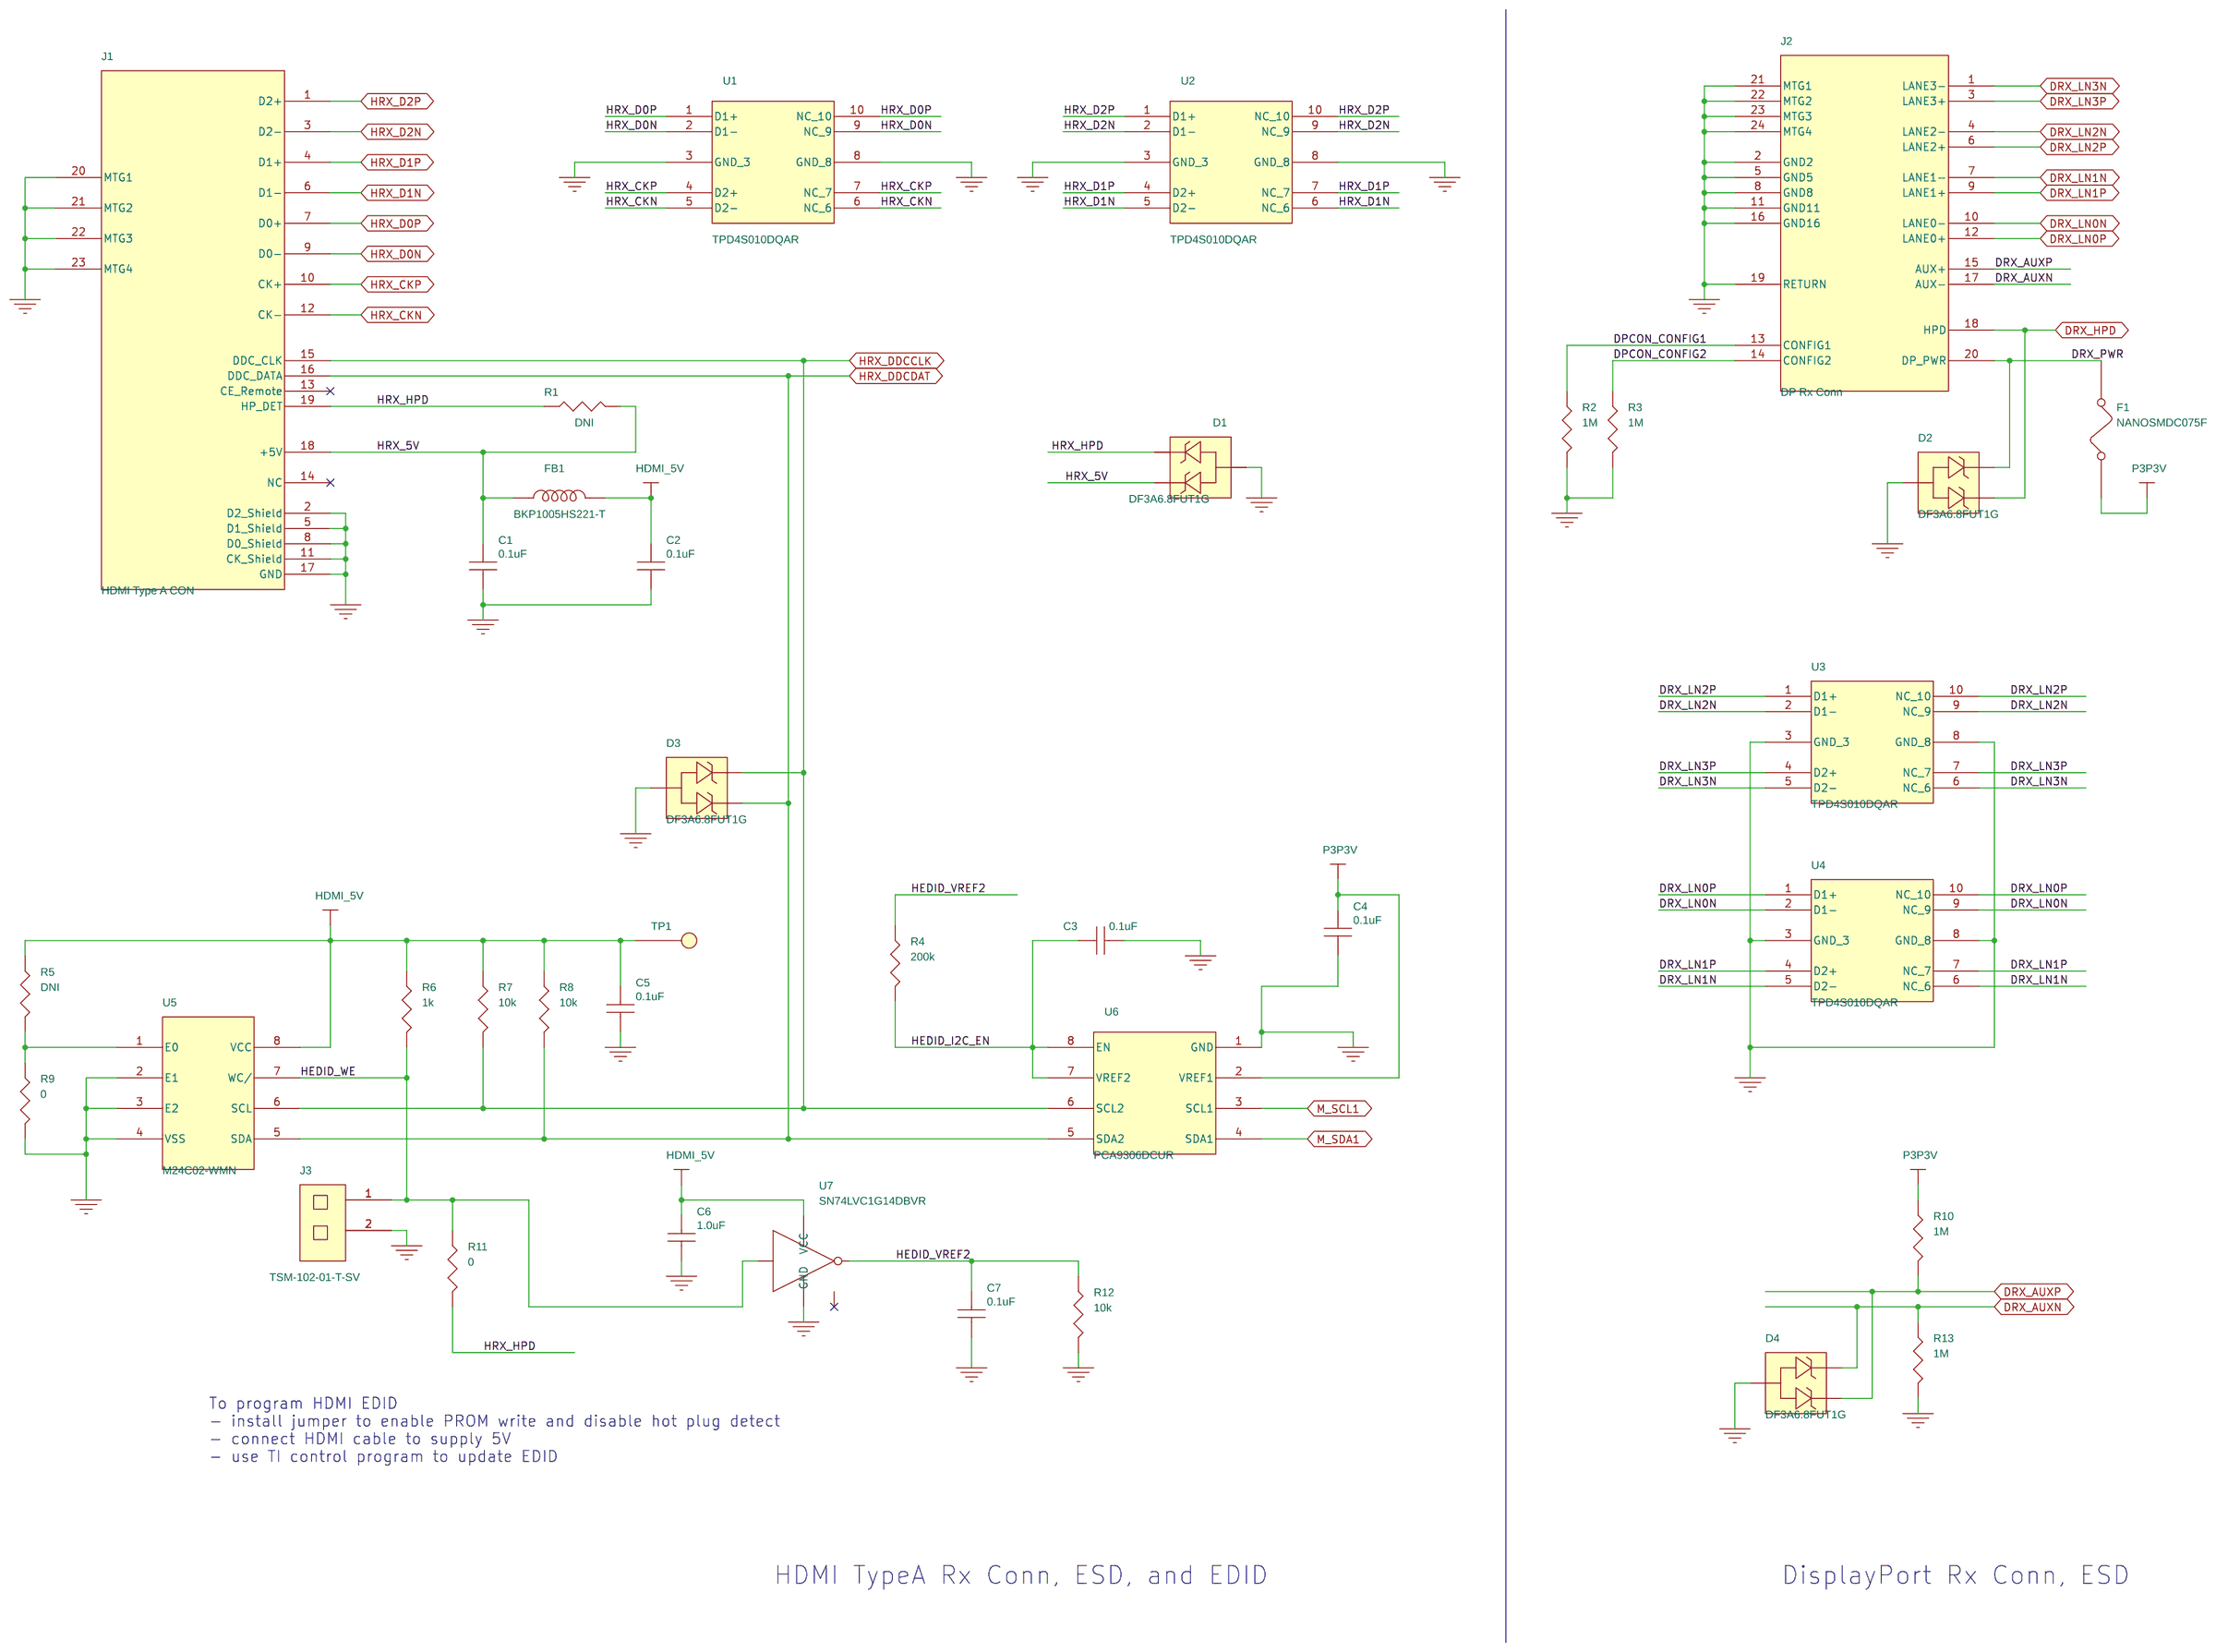
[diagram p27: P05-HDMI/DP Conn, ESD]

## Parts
sheet P05-HDMI/DP Conn, ESD
C1  0.1uF  [0402]
C2  0.1uF  [0402]
C3  0.1uF  [0402]
C4  0.1uF  [0402]
C5  0.1uF  [0402]
C6  1.0uF  [0402]
C7  0.1uF  [0402]
D1  DF3A6.8FUT1G  [SOT323]
D2  DF3A6.8FUT1G  [SOT323]
D3  DF3A6.8FUT1G  [SOT323]
D4  DF3A6.8FUT1G  [SOT323]
F1  NANOSMDC075F  [1206]
FB1  BKP1005HS221-T  [0402]
J1  HDMI Type A CON  [SMT]
J2  DP Rx Conn  [RA-Thru-hole]
J3  TSM-102-01-T-SV  [2POS-2p54mm]
R1  DNI  [0603]
R2  1M  [0603]
R3  1M  [0603]
R4  200k  [0603]
R5  DNI  [0603]
R6  1k  [0603]
R7  10k  [0402]
R8  10k  [0402]
R9  0  [0603]
R10  1M  [0603]
R11  0  [0402]
R12  10k  [0402]
R13  1M  [0603]
TP1  Testpoint  [24mil-plated]
U1  TPD4S010DQAR  [10-UFDFN]
U2  TPD4S010DQAR  [10-UFDFN]
U3  TPD4S010DQAR  [10-UFDFN]
U4  TPD4S010DQAR  [10-UFDFN]
U5  M24C02-WMN  [SO8]
U6  PCA9306DCUR  [8-VFSOP]
U7  SN74LVC1G14DBVR  [U_5_DBV]
sheet P06-IT6535 Input Output Ports
C8  18pF  [0402]
C9  18pF  [0402]
C10  1000pF  [0402]
C11  0.1uF  [0402]
C12  0.1uF  [0402]
C13  0.1uF  [0402]
C14  0.1uF  [0402]
J4  TSM-102-01-T-SV  [2POS-2p54mm]
R14  1M  [0603]
R15  0  [0402]
R16  0  [0402]
R17  10k  [0402]
R18  1.5k  [0603]
R19  DNI  [0402]
R20  4.7k  [0402]
R21  10k  [0402]
R22  500  [0603]
R23  3k  [0603]
R24  4.7K  [0402]
R25  22  [0402]
R26  22  [0402]
R27  22  [0402]
R28  1k  [0603]
R29  10k  [0402]
R30  10k  [0402]
R31  100k  [0603]
R32  0  [0402]
R33  22  [0402]
R34  22  [0402]
RP1  22  [0804]
RP2  22  [0804]
RP3  22  [0804]
RP4  22  [0804]
RP5  22  [0804]
RP6  22  [0804]
RP7  22  [0804]
RP8  22  [0804]
RP9  22  [0804]
RP10  22  [0804]
RP11  22  [0804]
RP12  22  [0804]
RP13  22  [0804]
RP14  22  [0804]
RP15  22  [0804]
TP2  Testpoint  [24mil-plated]
TP3  Testpoint  [24mil-plated]
TP4  Testpoint  [24mil-plated]
TP5  Testpoint  [24mil-plated]
TP6  Testpoint  [24mil-plated]
TP7  Testpoint  [24mil-plated]
TP8  Testpoint  [24mil-plated]
TP9  Testpoint  [24mil-plated]
TP10  Testpoint  [24mil-plated]
U8  IT6535  [TQFP-176]  (sections A,B,C)
U9  M24C02-WMN  [SO8]
U10  SN74CB3Q3306  [8TSSOP]
X1  27MHz  [4SMD]
sheet P07-IT6535 Pwr/Gnd
C15  22uF  [0805]
C16  0.1uF  [0402]
C17  0.1uF  [0402]
C18  0.1uF  [0402]
C19  0.1uF  [0402]
C20  0.1uF  [0402]
C21  10uF  [0603]
C22  0.1uF  [0402]
C23  0.1uF  [0402]
C24  0.1uF  [0402]
C25  10uF  [0603]
C26  0.1uF  [0402]
C27  0.1uF  [0402]
C28  0.1uF  [0402]
C29  0.1uF  [0402]
C30  22uF  [0805]
C31  0.1uF  [0402]
C32  0.1uF  [0402]
C33  0.1uF  [0402]
C34  0.1uF  [0402]
C35  0.1uF  [0402]
C36  0.1uF  [0402]
C37  10uF  [0603]
C38  0.1uF  [0402]
C39  0.1uF  [0402]
C40  0.1uF  [0402]
C41  0.1uF  [0402]
C42  10uF  [0603]
C43  0.1uF  [0402]
C44  0.1uF  [0402]
C45  0.1uF  [0402]
C46  10uF  [0603]
C47  0.1uF  [0402]
C48  0.1uF  [0402]
C49  10uF  [0603]
C50  0.1uF  [0402]
C51  0.1uF  [0402]
C52  0.1uF  [0402]
C53  10uF  [0603]
C54  0.1uF  [0402]
C55  0.1uF  [0402]
C56  0.1uF  [0402]
C57  10uF  [0603]
C58  0.1uF  [0402]
C59  0.1uF  [0402]
C60  1.0uF  [0402]
C61  0.1uF  [0402]
C62  1.0uF  [0402]
C63  0.1uF  [0402]
FB2  BKP1005EM221-T  [0402]
FB3  BKP1005EM221-T  [0402]
FB4  BKP1005EM221-T  [0402]
FB5  BKP1005EM221-T  [0402]
FB6  BKP1005EM221-T  [0402]
FB7  BKP1005EM221-T  [0402]
FB8  BKP1005EM221-T  [0402]
FB9  BKP1005EM221-T  [0402]
FB10  BKP1005EM221-T  [0402]
sheet P08-FPGA Bank 2A,3A,3B,4A
U11  5CEFA2F23C8N  [F484]  (sections A,B,C,D,E,F,G,H,I,J,K)
sheet P11-FPGA Pwr/Gnd
C65  1.0uF  [0402]
C66  0.1uF  [0402]
C67  10 nF  [4002]
C68  0.1uF  [0402]
C69  100uF  [1206]
C70  10uF  [0603]
C71  10uF  [0603]
C72  0.47uF  [0402]
C73  0.47uF  [0402]
C74  0.47uF  [0402]
C75  47nF  [0402]
C76  47nF  [0402]
C77  47nF  [0402]
C78  0.1uF  [0402]
C79  0.1uF  [0402]
C80  0.1uF  [0402]
C81  0.022uF  [0402]
C82  0.022uF  [0402]
C83  0.022uF  [0402]
C84  0.022uF  [0402]
C85  0.022uF  [0402]
C86  0.022uF  [0402]
C87  1.0uF  [0402]
C88  0.1uF  [0402]
C89  10 nF  [4002]
C90  10 nF  [0402]
C91  10 nF  [0402]
C92  10 nF  [0402]
C93  10 nF  [0402]
C94  10 nF  [0402]
C95  10 nF  [0402]
C96  4.7nF  [0402]
C97  4.7nF  [0402]
C98  4.7nF  [0402]
C99  4.7nF  [0402]
C100  4.7nF  [0402]
C101  4.7nF  [0402]
C102  4.7nF  [0402]
C103  4.7nF  [0402]
C104  10uF  [0603]
C105  10uF  [0603]
C106  0.1uF  [0402]
C107  0.1uF  [0402]
C108  0.1uF  [0402]
C109  0.1uF  [0402]
C110  0.1uF  [0402]
C111  0.1uF  [0402]
C112  0.1uF  [0402]
C113  0.1uF  [0402]
C114  0.1uF  [0402]
C115  0.1uF  [0402]
C116  10 nF  [0402]
C117  10 nF  [0402]
C118  10 nF  [0402]
C119  10 nF  [0402]
C120  10 nF  [0402]
C121  10 nF  [0402]
C122  10 nF  [0402]
C123  10 nF  [0402]
C124  10 nF  [0402]
C125  10 nF  [0402]
R56  2k  [0402]
sheet P15-Master ICE JTAG
U13  DLPC900 (master)  [516BGA]  (sections A,B,C,D,E,F,G,H,I,J)
sheet P17-Master Pwr/Gnd
C148  100uF  [1206]
C149  10uF  [0603]
C150  0.1uF  [0402]
C151  0.1uF  [0402]
C152  0.1uF  [0402]
C153  0.1uF  [0402]
C154  0.1uF  [0402]
C155  0.1uF  [0402]
C156  0.1uF  [0402]
C157  0.1uF  [0402]
C158  0.1uF  [0402]
C159  0.1uF  [0402]
C160  0.1uF  [0402]
C161  0.1uF  [0402]
C162  0.1uF  [0402]
C163  10uF  [0603]
C164  0.1uF  [0402]
C165  0.1uF  [0402]
C166  0.1uF  [0402]
C167  0.1uF  [0402]
C168  0.1uF  [0402]
C169  0.1uF  [0402]
C170  0.1uF  [0402]
C171  0.1uF  [0402]
C172  0.1uF  [0402]
C173  0.1uF  [0402]
C174  0.1uF  [0402]
C175  0.1uF  [0402]
C176  0.1uF  [0402]
C177  100uF  [1206]
C178  0.1uF  [0402]
C179  0.1uF  [0402]
C180  10uF  [0603]
C181  0.1uF  [0402]
C182  0.1uF  [0402]
C183  0.1uF  [0402]
C184  0.1uF  [0402]
C185  0.1uF  [0402]
C186  0.1uF  [0402]
C187  0.1uF  [0402]
C188  0.1uF  [0402]
C189  0.1uF  [0402]
C190  0.1uF  [0402]
C191  100uF  [1206]
C192  0.1uF  [0402]
C193  0.1uF  [0402]
C194  100uF  [1206]
C195  0.1uF  [0402]
C196  10uF  [0603]
C197  0.1uF  [0402]
C198  0.1uF  [0402]
C199  0.1uF  [0402]
C200  0.1uF  [0402]
C201  0.1uF  [0402]
C202  0.1uF  [0402]
C203  0.1uF  [0402]
C204  0.1uF  [0402]
C205  0.1uF  [0402]
C206  0.1uF  [0402]
C207  2.2uF  [0603]
C208  2.2uF  [0603]
C209  0.1uF  [0402]
C210  0.1uF  [0402]
C211  0.1uF  [0402]
C212  0.1uF  [0402]
C213  0.1uF  [0402]
C214  0.1uF  [0402]
C215  0.1uF  [0402]
C216  0.1uF  [0402]
C217  0.1uF  [0402]
C218  0.1uF  [0402]
C219  0.1uF  [0402]
FB11  BK1005HS431-T  [0402]
FB12  BK1005HS431-T  [0402]
FB13  BK1005HS431-T  [0402]
FB14  BK1005HS431-T  [0402]
FB15  BK1005HS431-T  [0402]
FB16  BK1005HS431-T  [0402]
FB17  BK1005HS431-T  [0402]
R141  0.36  [0402]
R142  1.0  [0402]
sheet P20-Slave Ext Flash Intf
U22  DLPC900 (slave)  [516BGA]  (sections A,B,C,D,E,F,G,H,I,J)
sheet P22-Slave Pwr/Gnd
C226  100uF  [1206]
C227  10uF  [0603]
C228  0.1uF  [0402]
C229  0.1uF  [0402]
C230  0.1uF  [0402]
C231  0.1uF  [0402]
C232  0.1uF  [0402]
C233  0.1uF  [0402]
C234  0.1uF  [0402]
C235  0.1uF  [0402]
C236  0.1uF  [0402]
C237  0.1uF  [0402]
C238  0.1uF  [0402]
C239  0.1uF  [0402]
C240  0.1uF  [0402]
C241  10uF  [0603]
C242  0.1uF  [0402]
C243  0.1uF  [0402]
C244  0.1uF  [0402]
C245  0.1uF  [0402]
C246  0.1uF  [0402]
C247  0.1uF  [0402]
C248  0.1uF  [0402]
C249  0.1uF  [0402]
C250  0.1uF  [0402]
C251  0.1uF  [0402]
C252  0.1uF  [0402]
C253  0.1uF  [0402]
C254  0.1uF  [0402]
C255  100uF  [1206]
C256  0.1uF  [0402]
C257  0.1uF  [0402]
C258  10uF  [0603]
C259  0.1uF  [0402]
C260  0.1uF  [0402]
C261  0.1uF  [0402]
C262  0.1uF  [0402]
C263  0.1uF  [0402]
C264  0.1uF  [0402]
C265  0.1uF  [0402]
C266  0.1uF  [0402]
C267  0.1uF  [0402]
C268  0.1uF  [0402]
C269  100uF  [1206]
C270  0.1uF  [0402]
C271  0.1uF  [0402]
C272  100uF  [1206]
C273  0.1uF  [0402]
C274  10uF  [0603]
C275  0.1uF  [0402]
C276  0.1uF  [0402]
C277  0.1uF  [0402]
C278  0.1uF  [0402]
C279  0.1uF  [0402]
C280  0.1uF  [0402]
C281  0.1uF  [0402]
C282  0.1uF  [0402]
C283  0.1uF  [0402]
C284  0.1uF  [0402]
C285  2.2uF  [0603]
C286  2.2uF  [0603]
C287  0.1uF  [0402]
C288  0.1uF  [0402]
C289  0.1uF  [0402]
C290  0.1uF  [0402]
C291  0.1uF  [0402]
C292  0.1uF  [0402]
C293  0.1uF  [0402]
C294  0.1uF  [0402]
C295  0.1uF  [0402]
C296  0.1uF  [0402]
C297  0.1uF  [0402]
FB18  BK1005HS431-T  [0402]
FB19  BK1005HS431-T  [0402]
FB20  BK1005HS431-T  [0402]
FB21  BK1005HS431-T  [0402]
FB22  BK1005HS431-T  [0402]
FB23  BK1005HS431-T  [0402]
FB24  BK1005HS431-T  [0402]
R166  0.36  [0402]
R167  1.0  [0402]

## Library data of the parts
C1-C5 C7 C11 C14 = CER_0.1UF_25V_10%_X5R_0402
C6 C60 C62 C65 C87 = CER_1.0UF_16V_10%_X5R_0402
D1-D4 = TVS_ZENER_DUAL_SOT323
F1 = Fuse_Polyswitch.75A
FB1 = FERRITE_BEAD_220_OHM_800mA_0402
J1 = HDMI_Connector_0
J2 = DP_CONN_RCPT_R_A_W_O_FLANGE
J3 J4 = TSM-102-01-T-SV_2POS_.1_SMD
R1 R5 R6 R28 = 1.0K_OHM_1_16W_5%_0402
R2 R3 R10 R13 R14 = 1M_OHM_1_10W_5%_0402
R4 = 200K_OHM_1_16W_5%_0402
R7 R8 R12 R17 R21 R29 R30 = 10K_OHM_1_10W_5%_0402
R9 = 0.0_OHM_1_10W_0603
R11 R15 R16 R32 = 0.0_OHM_1_10W_0402
TP1-TP10 = Testpoint
U1-U4 = TPD4S010DQA
U5 U9 = M24C08L_dsize
U6 = PCA9306DCUR
U7 = IC_SGL_SHMT-TRG_INV_SOT23-5
C8 C9 = CER_18PF_50V_5%_NP0_0402
C10 = CER_1000PF_25V_10%_X7R_0402
C12 C13 C16-C20 C22-C24 C26-C29 C31-C36 C38-C41 C43-C45 C47 C48 C50-C52 C54-C56 C58 C59 C61 C63 C66 C68 C78-C80 C88 C106-C115 C150-C162 C164-C176 C178 C179 C181-C190 C192 C193 C195 C197-C206 C209-C219 C228-C240 C242-C254 C256 C257 C259-C268 C270 C271 C273 C275-C284 C287-C297 = CER_0.1UF_16V_10%_X5R_0402
R18 = 1.5K_OHM_1_10W_5%_0603
R19 R20 R24 = 4.7K_OHM_1_10W_5%_0402
R22 = 500_OHM_0.15W_0.05%_0603
R23 = 3K_OHM_1_16W_5%_0402
R25-R27 R33 R34 = 22_OHM_1_10W_1%_0402
R31 = 100K_OHM_1_10W_1%_0603
RP1-RP15 = 22_OHM_ARR_1_32W_5%_0804
U8 = IT6535: Color: Default; Location X-Coordinate: 0; Location Y-Coordinate: 0; Power Pins Visible: False; Primitive: DEFAULT
U10 = IC_DUAL_FET_BUS_SWITCH_8-TSSOP
X1 = CRYSTAL_27MHZ_18PF_SMD
C15 C30 = CER_22UF_16V_10%_X5R_0805
C21 C25 C37 C49 C104 C105 = CER_10UF_16V_20%_X5R_0603
C42 C46 C53 C57 C149 C163 C180 C196 C227 C241 C258 C274 = CER_10UF_10V_20%_X5R_0603
FB2-FB10 = FERRITE_BEAD_220_OHM_1A_0402
U11 = FPGA_Cyclone5_5CEFA2F23C8N
C67 C89-C95 C116-C125 = CER_10_nF_25V_10%_X5R_0402
C69 C148 C177 C191 C194 C226 C255 C269 C272 = CER_100UF_6.3V_20%_X5R_1206
C70 C71 = CER_10UF_6.3V_20%_X5R_0402
C72-C74 = CER_0.47UF_10V_10%_X5R_0402
C75-C77 = CER_0.047UF_16V_10%_X7R_0402
C81-C86 = CER_0.022UF_10V_10%_X5R_0402
C96-C103 = CER_4.7nF_10V_10%_0402
R56 = 2K_OHM_1_10W_1%_0402
U13 U22 = DLPC900_910_datasheet
C207 C208 C285 C286 = CER_2.2UF_25V_10%_X5R_0603
FB11-FB24 = FERRITE_BEAD_430OHM_0402
R141 R166 = 0.36_OHM_1_8W_1%_0402
R142 R167 = 1.00_OHM_1_16W_1%_0402

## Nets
GND: C1.2 C2.2 C3.2 C4.2 C5.2 C6.2 C7.2 C8.1 C9.1 C10.2 C11.2 C14.2 C15.2 C16.2 C17.2 C18.2 C19.2 C20.2 C21.2 C22.2 C23.2 C24.2 C25.2 C26.2 C27.2 C28.2 C29.2 C30.2 C31.2 C32.2 C33.2 C34.2 C35.2 C36.2 C37.2 C38.2 C39.2 C40.2 C41.2 C42.2 C43.2 C44.2 C45.2 C46.2 C47.2 C48.2 C49.2 C50.2 C51.2 C52.2 C53.2 C54.2 C55.2 C56.2 C57.2 C58.2 C59.2 C60.2 C61.2 C62.2 C63.2 C65.2 C66.2 C67.2 C68.2 C69.2 C70.2 C71.2 C72.2 C73.2 C74.2 C75.2 C76.2 C77.2 C78.2 C79.2 C80.2 C81.2 C82.2 C83.2 C84.2 C85.2 C86.2 C87.2 C88.2 C89.2 C90.2 C91.2 C92.2 C93.2 C94.2 C95.2 C96.2 C97.2 C98.2 C99.2 C100.2 C101.2 C102.2 C103.2 C104.2 C105.2 C106.2 C107.2 C108.2 C109.2 C110.2 C111.2 C112.2 C113.2 C114.2 C115.2 C116.2 C117.2 C118.2 C119.2 C120.2 C121.2 C122.2 C123.2 C124.2 C125.2 C148.2 C149.2 C150.2 C151.2 C152.2 C153.2 C154.2 C155.2 C156.2 C157.2 C158.2 C159.2 C160.2 C161.2 C162.2 C163.2 C164.2 C165.2 C166.2 C167.2 C168.2 C169.2 C170.2 C171.2 C172.2 C173.2 C174.2 C175.2 C176.2 C177.2 C178.2 C179.2 C180.2 C181.2 C182.2 C183.2 C184.2 C185.2 C186.2 C187.2 C188.2 C189.2 C190.2 C191.2 C192.2 C193.2 C194.2 C195.2 C196.2 C197.2 C198.2 C199.2 C200.2 C201.2 C202.2 C203.2 C204.2 C205.2 C206.2 C207.2 C208.2 C209.2 C210.2 C211.2 C212.2 C213.2 C214.2 C215.2 C216.2 C217.2 C218.2 C219.2 C226.2 C227.2 C228.2 C229.2 C230.2 C231.2 C232.2 C233.2 C234.2 C235.2 C236.2 C237.2 C238.2 C239.2 C240.2 C241.2 C242.2 C243.2 C244.2 C245.2 C246.2 C247.2 C248.2 C249.2 C250.2 C251.2 C252.2 C253.2 C254.2 C255.2 C256.2 C257.2 C258.2 C259.2 C260.2 C261.2 C262.2 C263.2 C264.2 C265.2 C266.2 C267.2 C268.2 C269.2 C270.2 C271.2 C272.2 C273.2 C274.2 C275.2 C276.2 C277.2 C278.2 C279.2 C280.2 C281.2 C282.2 C283.2 C284.2 C285.2 C286.2 C287.2 C288.2 C289.2 C290.2 C291.2 C292.2 C293.2 C294.2 C295.2 C296.2 C297.2 D1.3 D2.3 D3.3 D4.3 J1.2(D2_Shield) J1.5(D1_Shield) J1.8(D0_Shield) J1.11(CK_Shield) J1.17(GND) J1.20(MTG1) J1.21(MTG2) J1.22(MTG3) J1.23(MTG4) J2.2(GND2) J2.5(GND5) J2.8(GND8) J2.11(GND11) J2.16(GND16) J2.19(RETURN) J2.21(MTG1) J2.22(MTG2) J2.23(MTG3) J2.24(MTG4) J3.2 J4.2 R2.2 R3.2 R9.2 R12.2 R13.2 R20.2 R21.2 R22.2 R23.2 R24.2 R31.2 R56.2 U1.3(GND) U1.8(GND) U2.3(GND) U2.8(GND) U3.3(GND) U3.8(GND) U4.3(GND) U4.8(GND) U5.2(E1) U5.3(E2) U5.4(VSS) U6.1(GND) U7.3(GND) U8.2(OVSS) U8.12(IVSS) U8.21(OVSS) U8.37(IVSS) U8.39(OVSS) U8.68(OVSS) U8.71(IVSS) U8.72(IVSS) U8.87(AVSS) U8.92(AVSS) U8.95(AVSS) U8.99(AVSS) U8.105(PVSS) U8.107(IVSS) U8.110(PGND) U8.113(DVSS18) U8.117(AGND) U8.123(AGND) U8.127(DVSS18) U8.130(PGND) U8.148(OVSS) U8.150(IVSS) U8.163(OVSS) U9.1(E0) U9.2(E1) U9.3(E2) U9.4(VSS) U10.4(GND) U11.A11(GND) U11.A21(GND) U11.AA3(GND) U11.AA4(GND) U11.AA6(GND) U11.AA11(GND) U11.AB1(GND) U11.AB2(GND) U11.AB9(GND) U11.AB14(GND) U11.AB19(GND) U11.B1(GND) U11.B2(GND) U11.B9(GND) U11.B14(GND) U11.C3(GND) U11.C4(GND) U11.C17(GND) U11.D1(GND) U11.D2(GND) U11.D5(GND) U11.D10(GND) U11.D20(GND) U11.E3(GND) U11.E4(GND) U11.E13(GND) U11.F1(GND) U11.F2(GND) U11.F5(GND) U11.F6(GND) U11.F16(GND) U11.G3(GND) U11.G4(GND) U11.G9(GND) U11.G19(GND) U11.H1(GND) U11.H2(GND) U11.H3(GND) U11.H4(GND) U11.H7(GND) U11.H12(GND) U11.H22(GND) U11.J3(GND) U11.J5(GND) U11.J15(GND) U11.J20(GND) U11.K1(GND) U11.K2(GND) U11.K4(GND) U11.K8(GND) U11.K10(GND) U11.K12(GND) U11.K14(GND) U11.L3(GND) U11.L5(GND) U11.L11(GND) U11.L13(GND) U11.L15(GND) U11.L21(GND) U11.M1(GND) U11.M2(GND) U11.M4(GND) U11.M10(GND) U11.M12(GND) U11.M14(GND) U11.N3(GND) U11.N5(GND) U11.N7(GND) U11.N11(GND) U11.N13(GND) U11.N15(GND) U11.N17(GND) U11.N22(GND) U11.P1(GND) U11.P2(GND) U11.P4(GND) U11.P10(GND) U11.R3(GND) U11.R13(GND) U11.T1(GND) U11.T2(GND) U11.T16(GND) U11.T21(GND) U11.U3(GND) U11.U4(GND) U11.U5(GND) U11.U9(GND) U11.V1(GND) U11.V2(GND) U11.V4(GND) U11.V7(GND) U11.V12(GND) U11.V17(GND) U11.V22(GND) U11.W3(GND) U11.W4(GND) U11.Y1(GND) U11.Y2(GND) U11.Y5(GND) U11.Y18(GND) U13.A1(GND) U13.A2(GND) U13.A3(GND) U13.A17(L_VDQPAD_1) U13.A18(L_VDQPAD_3) U13.A24(GND) U13.A25(GND) U13.A26(GND) U13.AA6(GND) U13.AA9(GND) U13.AA12(GND) U13.AA15(GND) U13.AA18(GND) U13.AA21(GND) U13.AB5(GND) U13.AB14(VTEST1) U13.AB15(VTEST2) U13.AB16(R_VDQPAD_3) U13.AB17(R_VDQPAD_1) U13.AB22(GND) U13.AC4(GND) U13.AC17(R_VDQPAD_6) U13.AC18(R_VDQPAD_4) U13.AC23(GND) U13.AD3(GND) U13.AD17(R_VDQPAD_2) U13.AD18(R_VDQPAD_0) U13.AD24(GND) U13.AE3(GND) U13.AE17(R_VDQPAD_7) U13.AE24(GND) U13.AE25(GND) U13.AF1(GND) U13.AF2(GND) U13.AF3(GND) U13.AF17(R_VDQPAD_5) U13.AF24(GND) U13.AF25(GND) U13.AF26(GND) U13.B1(GND) U13.B2(GND) U13.B3(GND) U13.B17(L_VDQPAD_5) U13.B18(L_VDQPAD_7) U13.B25(GND) U13.C3(GND) U13.C18(L_VDQPAD_2) U13.C24(GND) U13.D4(GND) U13.D17(L_VDQPAD_0) U13.D18(L_VDQPAD_6) U13.D23(GND) U13.E5(GND) U13.E15(VTEST3) U13.E16(VTEST4) U13.E17(L_VDQPAD_4) U13.E22(GND) U13.F6(GND) U13.F9(GND) U13.F12(GND) U13.F15(GND) U13.F18(GND) U13.F21(GND) U13.G5(GND) U13.J5(GND) U13.J6(GND) U13.J21(GND) U13.K5(LVDS_AVS1) U13.K26(PLLD_VAS) U13.L5(GND) U13.L12(GND) U13.L13(GND) U13.L14(GND) U13.L15(GND) U13.L23(PLLD_VSS) U13.L25(PLLM1_VAS) U13.M6(GND) U13.M11(GND) U13.M12(GND) U13.M13(GND) U13.M14(GND) U13.M15(GND) U13.M16(GND) U13.M21(GND) U13.M22(PLLM1_VSS) U13.N5(GND) U13.N11(GND) U13.N12(GND) U13.N13(GND) U13.N14(GND) U13.N15(GND) U13.N16(GND) U13.P11(GND) U13.P12(GND) U13.P13(GND) U13.P14(GND) U13.P15(GND) U13.P16(GND) U13.P24(PLLM2_VSS) U13.R5(GND) U13.R6(GND) U13.R11(GND) U13.R12(GND) U13.R13(GND) U13.R14(GND) U13.R15(GND) U13.R16(GND) U13.R24(PLLS_VAS) U13.R26(PLLM2_VAS) U13.T12(GND) U13.T13(GND) U13.T14(GND) U13.T15(GND) U13.U5(GND) U13.V5(LVDS_AVS2) U13.V6(GND) U13.V21(GND) U13.W5(GND) U13.Y5(GND) U22.A1(GND) U22.A2(GND) U22.A3(GND) U22.A17(L_VDQPAD_1) U22.A18(L_VDQPAD_3) U22.A24(GND) U22.A25(GND) U22.A26(GND) U22.AA6(GND) U22.AA9(GND) U22.AA12(GND) U22.AA15(GND) U22.AA18(GND) U22.AA21(GND) U22.AB5(GND) U22.AB14(VTEST1) U22.AB15(VTEST2) U22.AB16(R_VDQPAD_3) U22.AB17(R_VDQPAD_1) U22.AB22(GND) U22.AC4(GND) U22.AC17(R_VDQPAD_6) U22.AC18(R_VDQPAD_4) U22.AC23(GND) U22.AD3(GND) U22.AD17(R_VDQPAD_2) U22.AD18(R_VDQPAD_0) U22.AD24(GND) U22.AE3(GND) U22.AE17(R_VDQPAD_7) U22.AE24(GND) U22.AE25(GND) U22.AF1(GND) U22.AF2(GND) U22.AF3(GND) U22.AF17(R_VDQPAD_5) U22.AF24(GND) U22.AF25(GND) U22.AF26(GND) U22.B1(GND) U22.B2(GND) U22.B3(GND) U22.B17(L_VDQPAD_5) U22.B18(L_VDQPAD_7) U22.B25(GND) U22.C3(GND) U22.C18(L_VDQPAD_2) U22.C24(GND) U22.D4(GND) U22.D17(L_VDQPAD_0) U22.D18(L_VDQPAD_6) U22.D23(GND) U22.E5(GND) U22.E15(VTEST3) U22.E16(VTEST4) U22.E17(L_VDQPAD_4) U22.E22(GND) U22.F6(GND) U22.F9(GND) U22.F12(GND) U22.F15(GND) U22.F18(GND) U22.F21(GND) U22.G5(GND) U22.J5(GND) U22.J6(GND) U22.J21(GND) U22.K5(LVDS_AVS1) U22.K26(PLLD_VAS) U22.L5(GND) U22.L12(GND) U22.L13(GND) U22.L14(GND) U22.L15(GND) U22.L23(PLLD_VSS) U22.L25(PLLM1_VAS) U22.M6(GND) U22.M11(GND) U22.M12(GND) U22.M13(GND) U22.M14(GND) U22.M15(GND) U22.M16(GND) U22.M21(GND) U22.M22(PLLM1_VSS) U22.N5(GND) U22.N11(GND) U22.N12(GND) U22.N13(GND) U22.N14(GND) U22.N15(GND) U22.N16(GND) U22.P11(GND) U22.P12(GND) U22.P13(GND) U22.P14(GND) U22.P15(GND) U22.P16(GND) U22.P24(PLLM2_VSS) U22.R5(GND) U22.R6(GND) U22.R11(GND) U22.R12(GND) U22.R13(GND) U22.R14(GND) U22.R15(GND) U22.R16(GND) U22.R24(PLLS_VAS) U22.R26(PLLM2_VAS) U22.T12(GND) U22.T13(GND) U22.T14(GND) U22.T15(GND) U22.U5(GND) U22.V5(LVDS_AVS2) U22.V6(GND) U22.V21(GND) U22.W5(GND) U22.Y5(GND) ; also on sheet 2 3 4 6 7 8 9 10 12 13 14 15 16 17 18
AFE_ARSTZ: U8.74(SYSRSTN) ; also on sheet 4 18
DA_B0: RP8.7 ; also on sheet 5
DA_B1: RP8.8 ; also on sheet 5
DA_B2: RP7.5 ; also on sheet 5
DA_B3: RP7.6 ; also on sheet 5
DA_B4: RP7.7 ; also on sheet 5
DA_B5: RP7.8 ; also on sheet 5
DA_B6: RP6.5 ; also on sheet 5
DA_B7: RP6.6 ; also on sheet 5
DA_B8: RP6.7 ; also on sheet 5
DA_B9: RP6.8 ; also on sheet 5
DA_G0: RP5.5 ; also on sheet 5
DA_G1: RP5.6 ; also on sheet 5
DA_G2: RP5.7 ; also on sheet 5
DA_G3: RP5.8 ; also on sheet 5
DA_G4: RP4.5 ; also on sheet 5
DA_G5: RP4.6 ; also on sheet 5
DA_G6: RP4.7 ; also on sheet 5
DA_G7: RP4.8 ; also on sheet 5
DA_G8: RP3.5 ; also on sheet 5
DA_G9: RP3.6 ; also on sheet 5
DA_R0: RP3.7 ; also on sheet 5
DA_R1: RP3.8 ; also on sheet 5
DA_R2: RP2.5 ; also on sheet 5
DA_R3: RP2.6 ; also on sheet 5
DA_R4: RP2.7 ; also on sheet 5
DA_R5: RP2.8 ; also on sheet 5
DA_R6: RP1.5 ; also on sheet 5
DA_R7: RP1.6 ; also on sheet 5
DA_R8: RP1.7 ; also on sheet 5
DA_R9: RP1.8 ; also on sheet 5
DB_B0: R34.2 ; also on sheet 5
DB_B1: R33.2 ; also on sheet 5
DB_B2: RP15.5 ; also on sheet 5
DB_B3: RP15.6 ; also on sheet 5
DB_B4: RP15.7 ; also on sheet 5
DB_B5: RP15.8 ; also on sheet 5
DB_B6: RP14.5 ; also on sheet 5
DB_B7: RP14.6 ; also on sheet 5
DB_B8: RP14.7 ; also on sheet 5
DB_B9: RP14.8 ; also on sheet 5
DB_G0: RP13.5 ; also on sheet 5
DB_G1: RP13.6 ; also on sheet 5
DB_G2: RP13.7 ; also on sheet 5
DB_G3: RP13.8 ; also on sheet 5
DB_G4: RP12.5 ; also on sheet 5
DB_G5: RP12.6 ; also on sheet 5
DB_G6: RP12.7 ; also on sheet 5
DB_G7: RP12.8 ; also on sheet 5
DB_G8: RP11.5 ; also on sheet 5
DB_G9: RP11.6 ; also on sheet 5
DB_R0: RP11.7 ; also on sheet 5
DB_R1: RP11.8 ; also on sheet 5
DB_R2: RP10.5 ; also on sheet 5
DB_R3: RP10.6 ; also on sheet 5
DB_R4: RP10.7 ; also on sheet 5
DB_R5: RP10.8 ; also on sheet 5
DB_R6: RP9.5 ; also on sheet 5
DB_R7: RP9.6 ; also on sheet 5
DB_R8: RP9.7 ; also on sheet 5
DB_R9: RP9.8 ; also on sheet 5
DP_DDCSCL: R29.2 U8.79(DDCSCL) U9.6(SCL) U10.2(1A)
DP_DDCSDA: R30.2 U8.80(DDCSDA) U9.5(SDA) U10.5(2A)
DP_EDID_WE: J4.1 R28.2 R32.1 U9.7(WC/)
DP_RXAUXN: C13.1 U8.108(RXAUXN)
DP_RXAUXP: C12.1 U8.109(RXAUXP)
DPCON_CONFIG1: J2.13(CONFIG1) R2.1
DPCON_CONFIG2: J2.14(CONFIG2) R3.1
DPIICWR_OEZ: R32.2 U10.1(1~{OE}) U10.7(2~{OE})
DRX_AUXN: C13.2 D4.2 J2.17(AUX-) R13.1 U8.82(DCAUXN)
DRX_AUXP: C12.2 D4.1 J2.15(AUX+) R10.2 U8.83(DCAUXP)
DRX_HPD: D2.1 J2.18(HPD) R31.1 TP10.1 U8.81(HPD)
DRX_LN0N: J2.10(LANE0-) U4.2(D1-) U4.9(NC) U8.116(DRX0N)
DRX_LN0P: J2.12(LANE0+) U4.1(D1+) U4.10(NC) U8.115(DRX0P)
DRX_LN1N: J2.7(LANE1-) U4.5(D2-) U4.6(NC) U8.119(DRX1N)
DRX_LN1P: J2.9(LANE1+) U4.4(D2+) U4.7(NC) U8.118(DRX1P)
DRX_LN2N: J2.4(LANE2-) U3.2(D1-) U3.9(NC) U8.122(DRX2N)
DRX_LN2P: J2.6(LANE2+) U3.1(D1+) U3.10(NC) U8.121(DRX2P)
DRX_LN3N: J2.1(LANE3-) U3.5(D2-) U3.6(NC) U8.125(DRX3N)
DRX_LN3P: J2.3(LANE3+) U3.4(D2+) U3.7(NC) U8.124(DRX3P)
DRX_PWR: D2.2 F1.2 J2.20(DP_PWR)
F_RREF_TL: R56.1 U11.A1(RREF_TL)
F_VCCIO: C68.1 C104.1 C105.1 C106.1 C107.1 C108.1 C109.1 C110.1 C111.1 C112.1 C113.1 C114.1 C115.1 C116.1 C117.1 C118.1 C119.1 C120.1 C121.1 C122.1 C123.1 C124.1 C125.1 U11.A3(VCCBAT) U11.C10(VCCPD7A8A) U11.D8(VCCPD7A8A) U11.D14(VCCPD7A8A) U11.D16(VCCPD7A8A) U11.E1(VCCPD1A2A) U11.E11(VCCPD7A8A) U11.F8(VCCPGM) U11.J2(VCCPD1A2A) U11.R2(VCCPD1A2A) U11.R19(VCCPGM) U11.V8(VCCPGM) U11.W11(VCCPD3B4A) U11.W12(VCCPD3B4A) U11.W14(VCCPD3B4A) U11.W17(VCCPD3B4A) ; also on sheet 2 3 4 5
HDMI_5V: C2.1 C5.1 C6.1 FB1.2 R5.1 R6.1 R7.1 R8.1 R18.1 TP1.1 U5.8(VCC) U7.5(VCC)
HDMI_INTZ: R17.1 TP9.1 U8.75(INT#) ; also on sheet 18
HEDID_I2C_EN: C3.1 R4.2 U6.7(VREF2) U6.8(EN)
HEDID_VREF2: C7.1 R4.1 R12.1 U7.4
HEDID_WE: J3.1 R6.2 R11.1 U5.7(WC/) U7.2
HRX_5V: C1.1 D1.1 FB1.1 J1.18(+5V) R1.2
HRX_CKN: J1.12(CK-) U1.5(D2-) U1.6(NC) U8.90(HRXCM)
HRX_CKP: J1.10(CK+) U1.4(D2+) U1.7(NC) U8.91(HRXCP)
HRX_D0N: J1.9(D0-) U1.2(D1-) U1.9(NC) U8.93(HRX0M)
HRX_D0P: J1.7(D0+) U1.1(D1+) U1.10(NC) U8.94(HRX0P)
HRX_D1N: J1.6(D1-) U2.5(D2-) U2.6(NC) U8.97(HRX1M)
HRX_D1P: J1.4(D1+) U2.4(D2+) U2.7(NC) U8.98(HRX1P)
HRX_D2N: J1.3(D2-) U2.2(D1-) U2.9(NC) U8.101(HRX2M)
HRX_D2P: J1.1(D2+) U2.1(D1+) U2.10(NC) U8.102(HRX2P)
HRX_DDCCLK: D3.2 J1.15(DDC_CLK) R7.2 R15.1 U5.6(SCL) U6.6(SCL2)
HRX_DDCDAT: D3.1 J1.16(DDC_DATA) R8.2 R16.1 U5.5(SDA) U6.5(SDA2)
HRX_HPD: D1.2 J1.19(HP_DET) R1.1 R11.2
HRXDDCSCL: R15.2 U8.85(RXDDCSCL)
HRXDDCSDA: R16.2 U8.84(RXDDCSDA)
IT_DE_PIN: R26.1 U8.5(DE)
IT_EMEMVPP: R21.1 U8.49(EMEM_VPP)
IT_ENTEST: R20.1 U8.73(ENTEST)
IT_FIELD_PIN: R25.1 U8.3(FIELD)
IT_HS_PIN: RP8.3 U8.7(HSYNC)
IT_PCADR: R19.2 R24.1 U8.76(PCADR)
IT_PCLK: R27.1 U8.4(PCLK)
IT_PWR5V: C10.1 R18.2 R23.1 U8.86(PWR5V)
IT_REXT: R22.1 U8.103(REXT)
IT_VS_PIN: RP8.4 U8.6(VSYNC)
IT_XTALIN: C8.2 R14.1 U8.132(XTALIN) X1.3
IT_XTALOUT: C9.2 R14.2 U8.131(XTALOUT) X1.1
ITE_ASPVCC: C60.1 C61.1 FB9.2 U8.133(ASPVCC)
ITE_AVCC: C42.1 C43.1 C44.1 C45.1 FB4.2 U8.114(AVCC_1P8) U8.120(AVCC_1P8) U8.126(AVCC_1P8)
ITE_AVCC18: C53.1 C54.1 C55.1 C56.1 FB7.2 U8.88(AVCC18)
ITE_AVCC33: C49.1 C50.1 C51.1 C52.1 FB6.2 U8.89(AVCC33) U8.96(AVCC33) U8.100(AVCC33)
ITE_DE: R26.2 ; also on sheet 5
ITE_DVDD1P8: C46.1 C47.1 C48.1 FB5.2 U8.112(DVDD18) U8.128(DVDD18)
ITE_FIELD: R25.2 ; also on sheet 5
ITE_HS: RP8.6 ; also on sheet 5
ITE_IVDD1P8: C30.1 C31.1 C32.1 C33.1 C34.1 C35.1 C36.1 FB3.2 U8.11(IVDD_1P8) U8.36(IVDD_1P8) U8.69(IVDD_1P8) U8.70(IVDD_1P8) U8.106(IVDD_1P8) U8.149(IVDD_1P8)
ITE_OVDD3P3: C15.1 C16.1 C17.1 C18.1 C19.1 C20.1 C23.1 FB2.2 U8.1(OVDD_3P3) U8.20(OVDD_3P3) U8.38(OVDD_3P3) U8.67(OVDD_3P3) U8.147(OVDD_3P3) U8.162(OVDD_3P3)
ITE_PVCC: C57.1 C58.1 C59.1 FB8.2 U8.111(PVCC) U8.129(PVCC)
ITE_PVCC18: C62.1 C63.1 FB10.2 U8.104(PVCC18)
ITE_VS: RP8.5 ; also on sheet 5
M_1P1V_FILTER: C177.1 C178.1 FB11.1 FB13.1 FB15.1 FB17.1 R141.2
M_1P8V_A_FILTER: C191.1 C192.1 FB12.1 FB14.1 FB16.1 R142.2
M_SCL1: U6.3(SCL1) U8.77(PCSCL) U10.3(1B) ; also on sheet 9 14
M_SDA1: U6.4(SDA1) U8.78(PCSDA) U10.6(2B) ; also on sheet 9 14
P1P1V: C69.1 C70.1 C71.1 C72.1 C73.1 C74.1 C75.1 C76.1 C77.1 C78.1 C79.1 C80.1 C81.1 C82.1 C83.1 C84.1 C85.1 C86.1 C90.1 C91.1 C92.1 C93.1 C94.1 C95.1 C96.1 C97.1 C98.1 C99.1 C100.1 C101.1 C102.1 C103.1 C148.1 C149.1 C150.1 C151.1 C152.1 C153.1 C154.1 C155.1 C156.1 C157.1 C158.1 C159.1 C160.1 C161.1 C163.1 C164.1 C165.1 C166.1 C167.1 C168.1 C169.1 C170.1 C171.1 C173.1 C174.1 C175.1 C176.1 C226.1 C227.1 C228.1 C229.1 C230.1 C231.1 C232.1 C233.1 C234.1 C235.1 C236.1 C237.1 C238.1 C239.1 C241.1 C242.1 C243.1 C244.1 C245.1 C246.1 C247.1 C248.1 C249.1 C250.1 C251.1 C252.1 C254.1 R141.1 R166.1 U11.J4(VCC) U11.J10(VCC) U11.J12(VCC) U11.J14(VCC) U11.J16(VCC) U11.K3(VCC) U11.K5(VCC) U11.K11(VCC) U11.K13(VCC) U11.K15(VCC) U11.L4(VCC) U11.L10(VCC) U11.L12(VCC) U11.L14(VCC) U11.L16(VCC) U11.M11(VCC) U11.M13(VCC) U11.M15(VCC) U11.N4(VCC) U11.N10(VCC) U11.N12(VCC) U11.N14(VCC) U11.P3(VCC) U11.P11(VCC) U11.P13(VCC) U11.P15(VCC) U13.AA8(VDDC) U13.AA11(VDDC) U13.AA14(VDDC) U13.AA17(VDDC) U13.AA20(VDDC) U13.F7(VDDC) U13.F10(VDDC) U13.F13(VDDC) U13.F16(VDDC) U13.F19(VDDC) U13.G21(VDDC) U13.H6(VDDC) U13.K21(VDDC) U13.L6(VDDC) U13.L11(VDDC) U13.L16(VDDC) U13.N21(VDDC) U13.P6(VDDC) U13.T11(VDDC) U13.T16(VDDC) U13.T21(VDDC) U13.U6(VDDC) U13.W21(VDDC) U13.Y6(VDDC) U22.AA8(VDDC) U22.AA11(VDDC) U22.AA14(VDDC) U22.AA17(VDDC) U22.AA20(VDDC) U22.F7(VDDC) U22.F10(VDDC) U22.F13(VDDC) U22.F16(VDDC) U22.F19(VDDC) U22.G21(VDDC) U22.H6(VDDC) U22.K21(VDDC) U22.L6(VDDC) U22.L11(VDDC) U22.L16(VDDC) U22.N21(VDDC) U22.P6(VDDC) U22.T11(VDDC) U22.T16(VDDC) U22.T21(VDDC) U22.U6(VDDC) U22.W21(VDDC) U22.Y6(VDDC) ; also on sheet 6
P1P8V: C25.1 C26.1 C27.1 C28.1 C29.1 C180.1 C181.1 C182.1 C183.1 C184.1 C185.1 C186.1 C187.1 C188.1 C189.1 C190.1 C194.1 C196.1 C197.1 C198.1 C199.1 C200.1 C201.1 C202.1 C203.1 C204.1 C258.1 C259.1 C260.1 C261.1 C262.1 C263.1 C264.1 C265.1 C266.1 C267.1 C268.1 C272.1 C274.1 C275.1 C276.1 C277.1 C278.1 C279.1 C280.1 C281.1 C283.1 FB3.1 FB5.1 U13.AA5(LVDSAVD) U13.AA13(DRAMVDD) U13.AE1(LVDSAVD) U13.C1(LVDSAVD) U13.F5(LVDSAVD) U13.F14(DRAMVDD) U13.G6(LVDSAVD) U13.H5(DRAMVDD) U13.H21(DRAMVDD) U13.K6(LVDSAVD) U13.M5(LVDSAVD) U13.N6(DRAMVDD) U13.P5(LVDSAVD) U13.P21(DRAMVDD) U13.T5(LVDSAVD) U13.T6(DRAMVDD) U13.U21(DRAMVDD) U13.W6(LVDSAVD) U22.AA5(LVDSAVD) U22.AA13(DRAMVDD) U22.AE1(LVDSAVD) U22.C1(LVDSAVD) U22.F5(LVDSAVD) U22.F14(DRAMVDD) U22.G6(LVDSAVD) U22.H5(DRAMVDD) U22.H21(DRAMVDD) U22.K6(LVDSAVD) U22.M5(LVDSAVD) U22.N6(DRAMVDD) U22.P5(LVDSAVD) U22.P21(DRAMVDD) U22.T5(LVDSAVD) U22.T6(DRAMVDD) U22.U21(DRAMVDD) U22.W6(LVDSAVD) ; also on sheet 6 12
P1P8V_A: R142.1 R167.1 ; also on sheet 2
P1P8V_ITEA: C37.1 C38.1 C39.1 C40.1 C41.1 FB4.1 FB7.1 FB8.1 FB9.1 FB10.1 ; also on sheet 2
P2P5V_FAUXPLL: C65.1 C66.1 C67.1 C87.1 C88.1 C89.1 U11.D11(VCC_AUX) U11.D18(VCC_AUX) U11.E6(VCC_AUX) U11.F4(VCCA_FPLL) U11.H19(VCCA_FPLL) U11.M3(VCCA_FPLL) U11.T3(VCCA_FPLL) U11.T5(VCCA_FPLL) U11.U18(VCCA_FPLL) U11.W7(VCC_AUX) U11.W13(VCC_AUX) U11.W18(VCC_AUX) ; also on sheet 2
P3P3V: C4.1 C11.1 C14.1 C21.1 C22.1 C24.1 C207.1 C208.1 C209.1 C210.1 C211.1 C212.1 C213.1 C214.1 C215.1 C216.1 C217.1 C218.1 C219.1 C285.1 C286.1 C287.1 C288.1 C289.1 C290.1 C291.1 C292.1 C293.1 C294.1 C295.1 C296.1 C297.1 F1.1 FB2.1 FB6.1 R10.1 R17.2 R19.1 R28.1 R29.1 R30.1 U6.2(VREF1) U9.8(VCC) U10.8(VCC) U13.AA7(VDD33) U13.AA10(VDD33) U13.AA16(VDD33) U13.AA19(VDD33) U13.AE26(CFO_VDD33) U13.F8(VDD33) U13.F11(VDD33) U13.F17(VDD33) U13.F20(VDD33) U13.L21(VDD33) U13.R21(VDD33) U13.Y21(VDD33) U22.AA7(VDD33) U22.AA10(VDD33) U22.AA16(VDD33) U22.AA19(VDD33) U22.AE26(CFO_VDD33) U22.F8(VDD33) U22.F11(VDD33) U22.F17(VDD33) U22.F20(VDD33) U22.L21(VDD33) U22.R21(VDD33) U22.Y21(VDD33) ; also on sheet 2 3 6 7 8 9 10 11 12 13 14 15 16 17 18
PCLK: R27.2 ; also on sheet 5
PLLD_VAD_M1P8: C205.1 FB16.2 U13.K25(PLLD_VAD)
PLLD_VAD_S1P8: C282.1 FB23.2 U22.K25(PLLD_VAD)
PLLD_VDD_M1P1: C195.1 FB15.2 U13.L22(PLLD_VDD)
PLLD_VDD_S1P1: C273.1 FB22.2 U22.L22(PLLD_VDD)
PLLM1_VAD_M1P8: C172.1 FB12.2 U13.L24(PLLM1_VAD)
PLLM1_VAD_S1P8: C253.1 FB19.2 U22.L24(PLLM1_VAD)
PLLM1_VDD_M1P1: C206.1 FB17.2 U13.L26(PLLM1_VDD)
PLLM1_VDD_S1P1: C284.1 FB24.2 U22.L26(PLLM1_VDD)
PLLM2_VAD_M1P8: C193.1 FB14.2 U13.R25(PLLM2_VAD)
PLLM2_VAD_S1P8: C271.1 FB21.2 U22.R25(PLLM2_VAD)
PLLM2_VDD_M1P1: C179.1 FB13.2 U13.P23(PLLM2_VDD)
PLLM2_VDD_S1P1: C257.1 FB20.2 U22.P23(PLLM2_VDD)
PLLS_VAD_M1P1: C162.1 FB11.2 U13.R23(PLLS_VAD)
PLLS_VAD_S1P1: C240.1 FB18.2 U22.R23(PLLS_VAD)
QA_B0: RP8.2 U8.10(QA2)
QA_B1: RP8.1 U8.13(QA3)
QA_B2: RP7.4 U8.14(QA4)
QA_B3: RP7.3 U8.15(QA5)
QA_B4: RP7.2 U8.16(QA6)
QA_B5: RP7.1 U8.17(QA7)
QA_B6: RP6.4 U8.18(QA8)
QA_B7: RP6.3 U8.19(QA9)
QA_B8: RP6.2 U8.22(QA10)
QA_B9: RP6.1 U8.23(QA11)
QA_G0: RP5.4 U8.26(QA14)
QA_G1: RP5.3 U8.27(QA15)
QA_G2: RP5.2 U8.28(QA16)
QA_G3: RP5.1 U8.29(QA17)
QA_G4: RP4.4 U8.30(QA18)
QA_G5: RP4.3 U8.31(QA19)
QA_G6: RP4.2 U8.32(QA20)
QA_G7: RP4.1 U8.33(QA21)
QA_G8: RP3.4 U8.34(QA22)
QA_G9: RP3.3 U8.35(QA23)
QA_R0: RP3.2 U8.42(QA26)
QA_R1: RP3.1 U8.43(QA27)
QA_R2: RP2.4 U8.44(QA28)
QA_R3: RP2.3 U8.45(QA29)
QA_R4: RP2.2 U8.46(QA30)
QA_R5: RP2.1 U8.47(QA31)
QA_R6: RP1.4 U8.48(QA32)
QA_R7: RP1.3 U8.50(QA33)
QA_R8: RP1.2 U8.51(QA34)
QA_R9: RP1.1 U8.52(QA35)
QB_B0: R34.1 U8.141(QB2)
QB_B1: R33.1 U8.142(QB3)
QB_B2: RP15.4 U8.143(QB4)
QB_B3: RP15.3 U8.144(QB5)
QB_B4: RP15.2 U8.145(QB6)
QB_B5: RP15.1 U8.146(QB7)
QB_B6: RP14.4 U8.151(QB8)
QB_B7: RP14.3 U8.152(QB9)
QB_B8: RP14.2 U8.153(QB10)
QB_B9: RP14.1 U8.154(QB11)
QB_G0: RP13.4 U8.155(QB14)
QB_G1: RP13.3 U8.156(QB15)
QB_G2: RP13.2 U8.157(QB16)
QB_G3: RP13.1 U8.158(QB17)
QB_G4: RP12.4 U8.159(QB18)
QB_G5: RP12.3 U8.160(QB19)
QB_G6: RP12.2 U8.161(QB20)
QB_G7: RP12.1 U8.164(QB21)
QB_G8: RP11.4 U8.165(QB22)
QB_G9: RP11.3 U8.166(QB23)
QB_R0: RP11.2 U8.167(QB26)
QB_R1: RP11.1 U8.168(QB27)
QB_R2: RP10.4 U8.169(QB28)
QB_R3: RP10.3 U8.170(QB29)
QB_R4: RP10.2 U8.171(QB30)
QB_R5: RP10.1 U8.172(QB31)
QB_R6: RP9.4 U8.173(QB32)
QB_R7: RP9.3 U8.174(QB33)
QB_R8: RP9.2 U8.175(QB34)
QB_R9: RP9.1 U8.176(QB35)
S_1P1V_FILTER: C255.1 C256.1 FB18.1 FB20.1 FB22.1 FB24.1 R166.2
S_1P8V_A_FILTER: C269.1 C270.1 FB19.1 FB21.1 FB23.1 R167.2
N20158334: R5.2 R9.1 U5.1(E0)
N20187524: TP3.1 U8.134(SCK_DCLK_MCLK)
N20187527: TP2.1 U8.135(WS_DR0)
N20187534: TP4.1 U8.136(I2S0_DL0)
N20187537: TP5.1 U8.137(I2S1_DR1)
N20187540: TP6.1 U8.138(I2S2_DL1)
N20187543: TP7.1 U8.139(I2S3_DR2)
N20187546: TP8.1 U8.140(SPDIF_DL2)

Not connected (* = marked no-connect by the designer): J1 13(CE_Remote)* 14(NC)*; U7 1*; U8 8(QA0) 9(QA1) 24(QA12)* 25(QA13)* 40(QA24)* 41(QA25)* 53(NC)* 54(NC)* 55(NC)* 56(NC)* 57(NC)* 58(NC)* 59(NC)* 60(NC)* 61(NC)* 62(NC)* 63(NC)* 64(NC)* 65(NC)* 66(NC)*; U11 A17(NC)* A18(NC)* A19(NC)* A20(NC)* A22(NC)* B3(DNU)* B4(DNU)* B17(NC)* B18(NC)* B20(NC)* B21(NC)* B22(NC)* C18(NC)* C19(NC)* C20(NC)* C21(NC)* D19(NC)* D21(NC)* D22(NC)* E17(DNU)* E19(NC)* E20(NC)* E21(NC)* E22(NC)* F18(NC)* F19(NC)* F20(NC)* F22(NC)* G20(NC)* G21(NC)* G22(NC)* H20(NC)* H21(NC)* J21(NC)* J22(NC)* L9(DNU)* V11(NC)* Y6(NC)*; X1 2* 4*

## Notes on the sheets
sheet 19
- COMPUTER GENERATED DRAWING - DO NOT REVISE MANUALLY
- NOTES, UNLESS OTHERWISE SPECIFIED:
- REVISIONS
- REV
- DESCRIPTION
- DATE
- APPROVED
- 1.
- The netname "P12V" represents connection to the +12V power plane.
- A
- ECO 2137507: Initial Release
- 11/1/2013
- NG
- 2.
- The netname "P3P3V" represents connection to the +3.3V power plane.
- 3.
- The netname "P1P8V" represents connection to the +1.8V digital power plane.
- B
- ECO 2140137: Updated to rev B
- 2/18/2014
- NG
- C
- ECO 2141055: Updated to rev C
- 4.
- The netname "P1P1V" represents connection to the +1.1V  power plane.
- 4/8/2014
- NG
- D
- ECO 2142175: Updated to rev D
- 5/28/2014
- NG
- 5.
- The netname "P1P8V_ITEA" represents connection to the +1.8V ITE6535 analog supply power plane.
- 6.
- The netname "F_VCCIO" represents connection to the +3V FPGA Vccio power plane.
- E
- ECO 2144118: Updated to rev E
- 8/8/2014
- NG
- 7.
- The netname "P2P5V_FAUXPLL" represents connection to the +2.5V FPGA aux/pll power plane.
- 8.
- The netname "P1P8V_A" represents connection to the +1.8V controller analog supply power plane.
- 9.
- The netname "GND" represents connection to the ground plane.
- 10.
- A "Z" suffix on a signal name indicates an active low signal.
- 11.
- All components with designators "U*", "Q*", and "D*" are electrostatic discharge sensitive.
- xxxxxxxx
- TI Confidential
           NDA Restrictions
  Property of Texas Instruments Only
- 2513535
- 0314PO
sheet 20
- Table of Contents
- Page
- Description
- 1
- Title
- 2
- Import Notice for TI Products
- 3
- Table Of Contents
- 4
- Block Diagram
- 5
- HDMI, DisplayPort Input/ESD
- 6
- IT6535 Input/Ouput Ports
- 7
- IT6535 Power/Ground Bypass
- 8
- FPGA Bank 2A,3A,3B,4A
- 9
- FPGA Bank 5A,5B,7A,8A
- 10
- FPGA Configuration
- 11
- FPGA Power/Ground Bypass
- 12
- Master Controller Video, DMD, DAD in/out ports
- 13
- Master Controller: USB, Reset/Clock, SSP0
- 14
- Master Controller: 128Mb x 3 flash interface
- 15
- Master Controller: JTAG, ICE interface
- 16
- Master Controller: I2C, Dual Controller ports, Trigger GPIOs
- 17
- Master Controller: Power/Ground Bypass
- 18
- Slave Controller: Video, DMD in/out ports
- 19
- Slave Controller: Reset/Clock Input, ICE, JTAG
- 20
- Slave Controller: 128Mb x 3 flash interface
- 21
- Slave Controller: I2C, Dual Controller, GPIOs
- 22
- Slave Controller: Power/Ground Bypass
- 23
- DMD Flex Connector
- 24
- Power Conv: 12V -->1.1V, 1.8V, 3.3V switchers
- 25
- Power Conv: FPGA Vccio, LDOs
- 26
- Input/output triggers, LED driver connector
- 27
- Posense, Powergood, 20MHz distribution
- 28
- Notes & Revision History
- TI Confidential
           NDA Restrictions
  Property of Texas Instruments Only
sheet 21
- I2C Ext
  Connector
  Page 16
- LED driver
  Conn
  Page 26
- 128Mb Flash x 3
  Page 14
- Ex Trigger
  Conn
  Page 26
- USB Jack &
  ESD Protection
  Page 13
- LED driver
  GPIO
  Page 16
- Ext Memory
  Interface
  Page 14
- Ext Trigger
  Interface
  Page 16
- I2C
  Page 16
- 3.3V
- FPGA
  Config
  Page 10
- Pwr/Gnd
  Bypass
  Page 17
- USB
  Page 13
- DisplayPort
  EDID
  Page 6
- FPGA
  Page 8,9,10,11
- HDMI EDID
  Page 5
- HDMI Type A
  Connector
  Page 5
- Master
  Controller
  Pixel Data
- Odd/Even
  Pixel Input
  Page 12
- DLPC900
  Master
- DMD LVDS
  Data Out
  Page 12
- HDMI Receiver
  IT6535
  Page 6, 7
- DMD Flex
  Connection
  Page 23
- ESD
  Protection
  Page 5
- DisplayPort
  Connector
  Page 5
- Spare
  GPIOs
- GPIOs to
  FPGA
  Page 16
- Master
  Strap Pin
  Page 16
- DAD
  Control
  Page 12
- Slave
  Controller
  Pixel Data
- Powergood,
  Reset, Clk In
  Page 13
- Dual
  Controller
  Support
  Page 16
- SCP (SSP0)
  Interface
  Page 13
- ARM uP ICE
  Page 15
- TO
  FPGA
- Realview ICE
  Page 15
- 20MHz Osc
  Page 27
- Powergood,
  Reset, Clk In
  Page 19
- Dual
  Controller
  Support
  Page 21
- SCP (SSP0)
  Interface
  Page 19
- ARM uP ICE
  Page 19
- Odd/Even
  Pixel Input
  Page 18
- Pwr/Gnd
  Bypass
  Page 22
- 3.3V to 1.8V
  HDMI Rx Analog
- 3.3V to 2.5V
  FPGA Aux
- 12V to 3V
  FPGA IO
- DLPC900
  Slave
- DMD LVDS
  Data Out
  Page 18
- 12V Input
  Page 24
- 12V to 3.3V
- Slave
  Strap Pin
  Page 21
- POSENSE &
  PWRGOOD
  Generation
  Page 27
- 3.3V to 1.8V
  Controller
  Analog
- Ext Memory
  Interface
  Page 20
- 12V Monitor
- 12V to 1.1V
  Controller
  Core
- 1.1V Controller & FPGA Core
  1.8V digital
  1.8V Controller Analog
  1.8V HDMI Rx Analog
  2.5V FPGA Aux Pwr
  3.0V FPGA VCCio
  3.3V HDMI, IO power
- 128Mb Flash x 3
  Page 20
- 12V to 1.8V
- Power Conversion
  Page 24, 25
- TI Confidential
           NDA Restrictions
  Property of Texas Instruments Only
sheet 22
- Apply a crystal input
  even audio function
  is not used per ITE
  recommandation
- Must connect I2C and interrupt
  to controller for register setup
- I2C address select
  low = 0xB0
  high = 0xB2
- HDMI receiver input/output
sheet 23
- REVISION HISTORY
- Rev A
- PAGES - ALL
- - initial rev
- Rev B
- PAGE 27
- - new part for C360
- PAGE 26
- - relocated S_TP17 and S_TP18
- PAGE 24
- - new part for R179
- - removed C315, bulk cap not needed
- PAGE 25
- - new part for L4
- PAGE 10
- - new part for U12
- Rev C
- PAGES for U13 & U22
- - update pin name to match datasheet
- PAGE 15
- - add comments for usage of R117 & R118
- Rev D
- Remove references to DLPC910
- Rev E
- Updated U7
sheet 24
- 3.3V IO
- Digital logic core
- DP analog frontend
- Logic power for analog frontend
- 3.3V HDMI RX analog frontend
- 1.8V HDMI RX analog frontend
- DP Rx PLL power
- Crystal and audio PLL
- HDMI Rx PLL power
- HDMI receiver power/gnd bypass
sheet 25
- FPGA Pwr/Gnd
sheet 26
- Slave Controller Pwr Gnd
sheet 27
- Master Controller Pwr Gnd
sheet 28
- To program HDMI EDID
  - install jumper to enable PROM write and disable hot plug detect
  - connect HDMI cable to supply 5V
  - use TI control program to update EDID
- HDMI TypeA Rx Conn, ESD, and EDID
- DisplayPort Rx Conn, ESD
